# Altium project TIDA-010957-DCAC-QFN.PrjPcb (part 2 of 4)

## Sheet TIDA-010957-DCAC-Switching-Stage-GaN.SchDoc
size 558 x 431 mm; Date: Not shown in title block; ApprovedBy: Not shown in title block; CheckedBy: Not shown in title block; Author: Not shown in title block; CompanyName: Not shown in title block; Engineer: Not shown in title block; Organization: Not shown in title block; Address1: Not shown in title block; Address2: Not shown in title block; Address3: Not shown in title block; Address4: Not shown in title block; DocumentNumber: 1; Revision: Use project parameter SCH_Rev; SheetNumber: 12; SheetTotal: 12; PageSetup: Record=PageOptions¦CenterHorizontal=True¦CenterVertical=True¦PrintScale=1.00¦XCorrection=1.00¦YCorrection=1.00¦PrintKind=0¦BorderSize=5000000¦LeftOffset=0¦BottomOffset=0¦Orientation=2¦PaperLength=1000¦PaperWidth=1000¦Scale=100¦PaperSource=15¦PrintQuality=600¦MediaType=1¦DitherType=10¦PaperKind=Letter¦PrintScaleMode=1
Used 4 times, as channels N, L1, L2, L3. Parts and nets are listed once, with the designators drawn on the sheet.
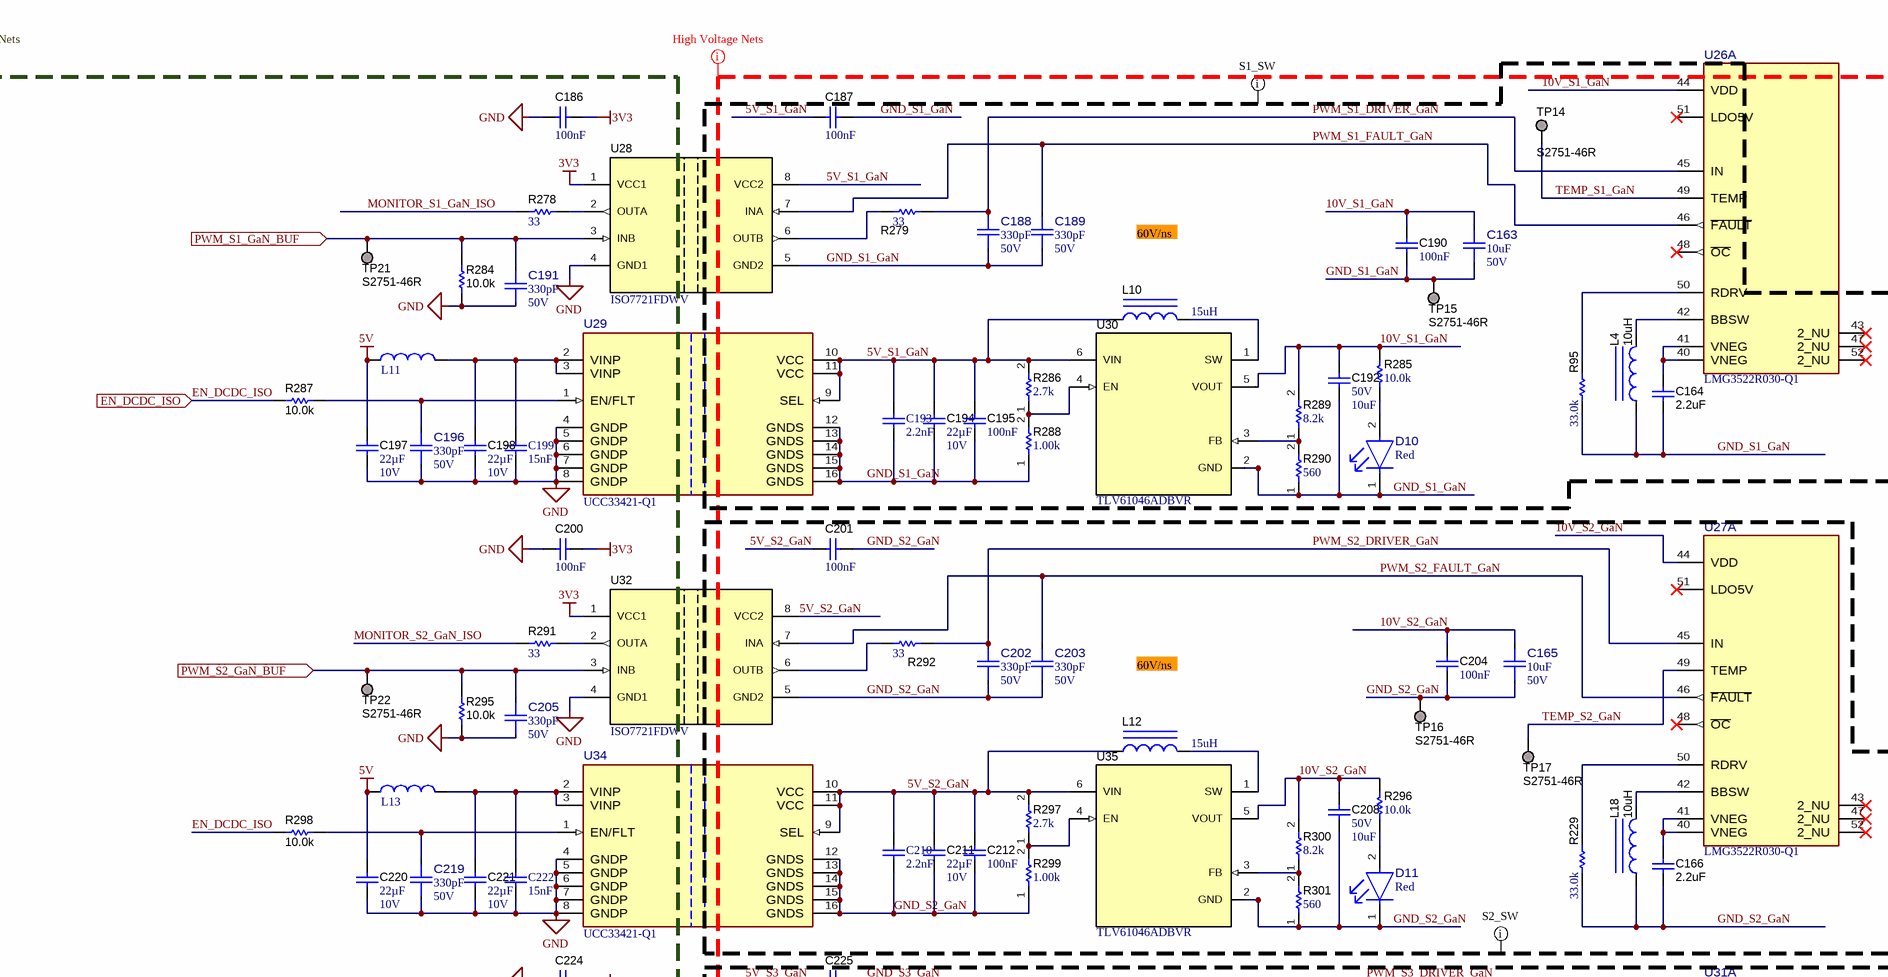
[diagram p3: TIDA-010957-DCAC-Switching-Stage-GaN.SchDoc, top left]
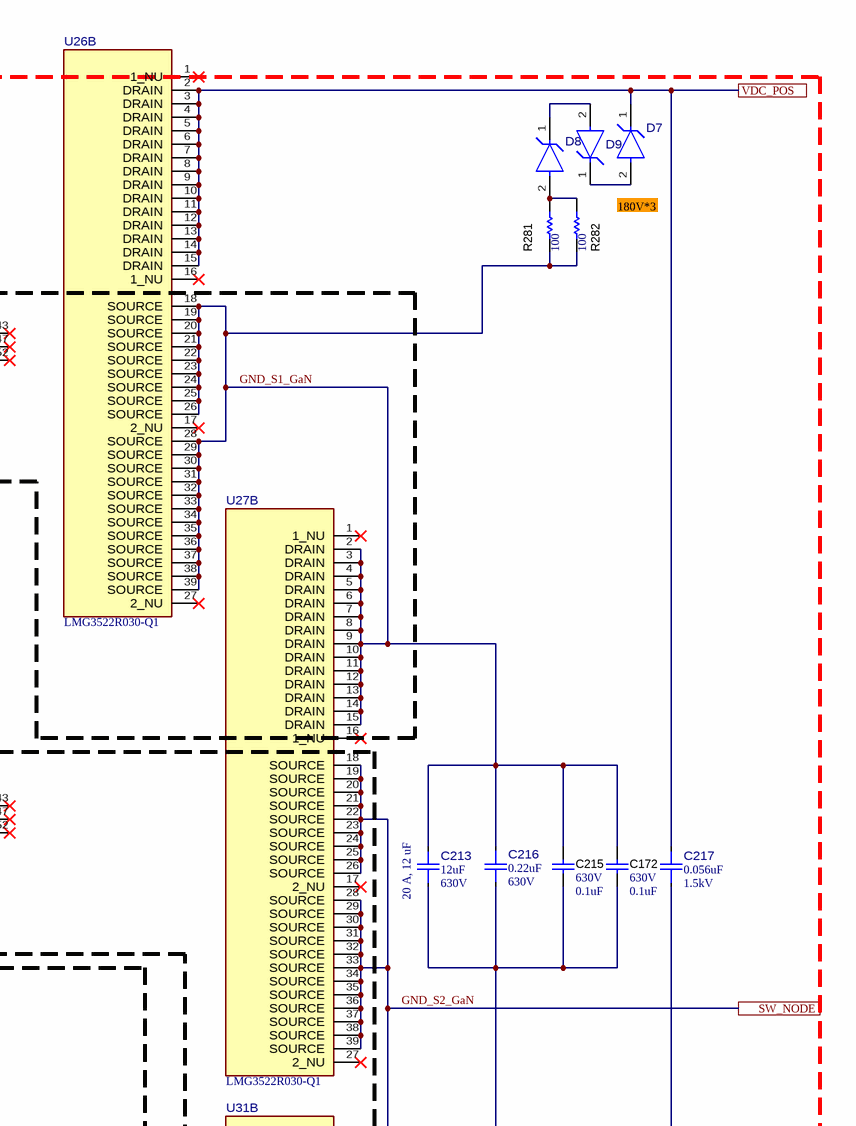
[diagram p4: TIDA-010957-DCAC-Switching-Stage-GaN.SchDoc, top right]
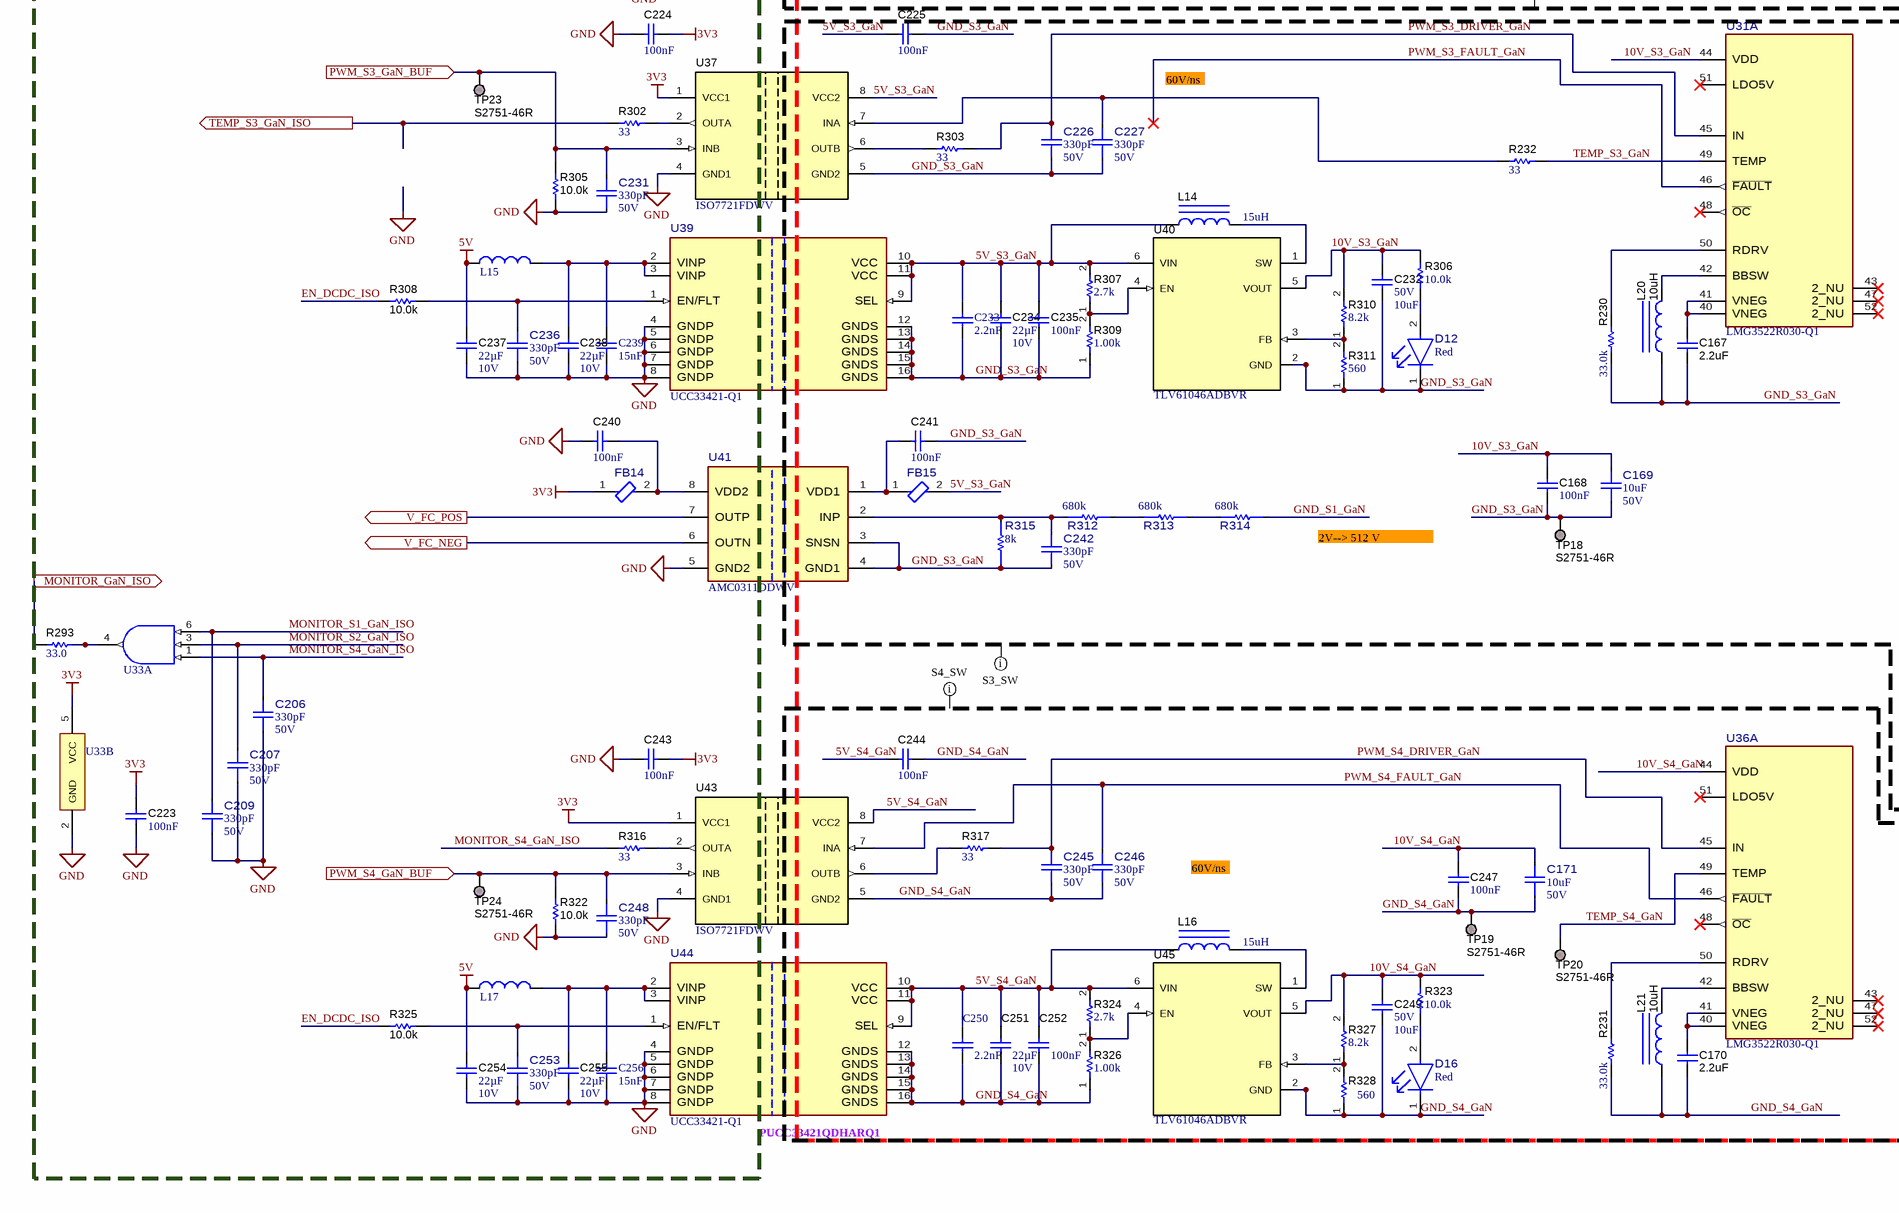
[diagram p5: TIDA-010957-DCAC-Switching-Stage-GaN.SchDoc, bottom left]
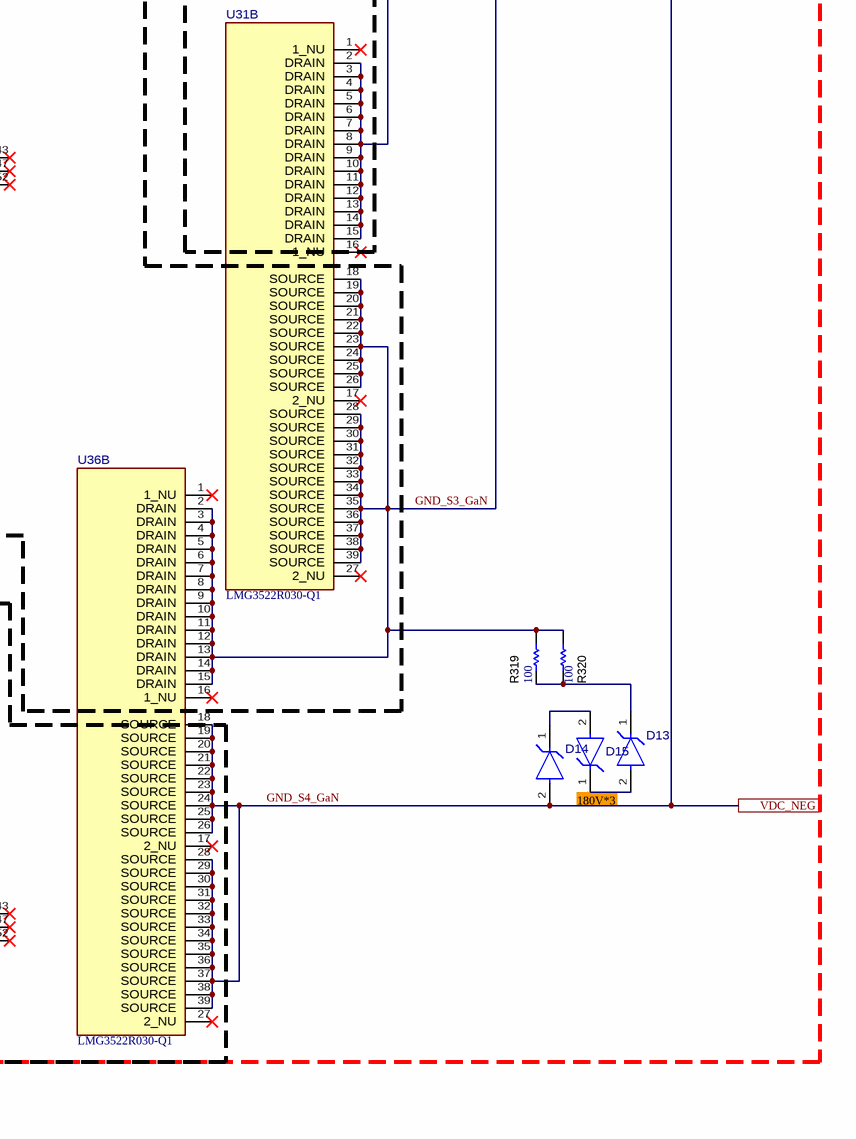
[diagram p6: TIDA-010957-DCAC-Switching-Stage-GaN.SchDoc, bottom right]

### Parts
C163  ValueDisplayed: 10uF  VDC_V: 50V  [FP-GRM21BR61H106ME43L_0805-MFG]  (hidden comment: GRM21BR61H106ME43L)
C164  ValueDisplayed: 2.2uF  [0805_HV]  (hidden comment: GRM21BR71E225KA73L)
C165  ValueDisplayed: 10uF  VDC_V: 50V  [FP-GRM21BR61H106ME43L_0805-MFG]  (hidden comment: GRM21BR61H106ME43L)
C166  ValueDisplayed: 2.2uF  [0805_HV]  (hidden comment: GRM21BR71E225KA73L)
C167  ValueDisplayed: 2.2uF  [0805_HV]  (hidden comment: GRM21BR71E225KA73L)
C168  Cap_F: 100nF  [0603]  (hidden comment: 06033C104JAT2A)
C169  ValueDisplayed: 10uF  VDC_V: 50V  [FP-GRM21BR61H106ME43L_0805-MFG]  (hidden comment: GRM21BR61H106ME43L)
C170  ValueDisplayed: 2.2uF  [0805_HV]  (hidden comment: GRM21BR71E225KA73L)
C171  ValueDisplayed: 10uF  VDC_V: 50V  [FP-GRM21BR61H106ME43L_0805-MFG]  (hidden comment: GRM21BR61H106ME43L)
C172  VDC_V: 630V  ValueDisplayed: 0.1uF  [1812_254]  (hidden comment: C1812X104KBRACTU)
C186  Cap_F: 100nF  [0603]  (hidden comment: 06033C104JAT2A)
C187  Cap_F: 100nF  [0603]  (hidden comment: 06033C104JAT2A)
C188  ValueDisplayed: 330pF  VDC_V: 50V  [FP-CGA3E2C0G1H331J080AA_0603-MFG]  (hidden comment: CGA3E2C0G1H331J080AA)
C189  ValueDisplayed: 330pF  VDC_V: 50V  [FP-CGA3E2C0G1H331J080AA_0603-MFG]  (hidden comment: CGA3E2C0G1H331J080AA)
C190  Cap_F: 100nF  [0603]  (hidden comment: 06033C104JAT2A)
C191  ValueDisplayed: 330pF  VDC_V: 50V  [FP-CGA3E2C0G1H331J080AA_0603-MFG]  (hidden comment: CGA3E2C0G1H331J080AA)
C192  VDC_V: 50V  ValueDisplayed: 10uF  [1206_180]  (hidden comment: GRT31CR61H106KE01L)
C193  Cap_F: 2.2nF  [WCAP-CSGP_0402_L1W0.5H0.5]  (hidden comment: 885012205063)
C194  Cap_F: 22µF  VDC_V: 10V  [0805_HV]  (hidden comment: GRM21BZ71A226ME15L)
C195  Cap_F: 100nF  [0603]  (hidden comment: 06033C104JAT2A)
C196  ValueDisplayed: 330pF  VDC_V: 50V  [FP-CGA3E2C0G1H331J080AA_0603-MFG]  (hidden comment: CGA3E2C0G1H331J080AA)
C197  Cap_F: 22µF  VDC_V: 10V  [0805_HV]  (hidden comment: GRM21BZ71A226ME15L)
C198  Cap_F: 22µF  VDC_V: 10V  [0805_HV]  (hidden comment: GRM21BZ71A226ME15L)
C199  Cap_F: 15nF  [WCAP-CSGP_0402_L1W0.5H0.5]  (hidden comment: 885012205051)
C200  Cap_F: 100nF  [0603]  (hidden comment: 06033C104JAT2A)
C201  Cap_F: 100nF  [0603]  (hidden comment: 06033C104JAT2A)
C202  ValueDisplayed: 330pF  VDC_V: 50V  [FP-CGA3E2C0G1H331J080AA_0603-MFG]  (hidden comment: CGA3E2C0G1H331J080AA)
C203  ValueDisplayed: 330pF  VDC_V: 50V  [FP-CGA3E2C0G1H331J080AA_0603-MFG]  (hidden comment: CGA3E2C0G1H331J080AA)
C204  Cap_F: 100nF  [0603]  (hidden comment: 06033C104JAT2A)
C205  ValueDisplayed: 330pF  VDC_V: 50V  [FP-CGA3E2C0G1H331J080AA_0603-MFG]  (hidden comment: CGA3E2C0G1H331J080AA)
C206  ValueDisplayed: 330pF  VDC_V: 50V  [FP-CGA3E2C0G1H331J080AA_0603-MFG]  (hidden comment: CGA3E2C0G1H331J080AA)
C207  ValueDisplayed: 330pF  VDC_V: 50V  [FP-CGA3E2C0G1H331J080AA_0603-MFG]  (hidden comment: CGA3E2C0G1H331J080AA)
C208  VDC_V: 50V  ValueDisplayed: 10uF  [1206_180]  (hidden comment: GRT31CR61H106KE01L)
C209  ValueDisplayed: 330pF  VDC_V: 50V  [FP-CGA3E2C0G1H331J080AA_0603-MFG]  (hidden comment: CGA3E2C0G1H331J080AA)
C210  Cap_F: 2.2nF  [WCAP-CSGP_0402_L1W0.5H0.5]  (hidden comment: 885012205063)
C211  Cap_F: 22µF  VDC_V: 10V  [0805_HV]  (hidden comment: GRM21BZ71A226ME15L)
C212  Cap_F: 100nF  [0603]  (hidden comment: 06033C104JAT2A)
C213  ValueDisplayed: 12uF  VDC_V: 630V  [FP-B32676G6126K000_RADIAL-MFG]  (hidden comment: B32676G6126K000)
C215  VDC_V: 630V  ValueDisplayed: 0.1uF  [1812_254]  (hidden comment: C1812X104KBRACTU)
C216  ValueDisplayed: 0.22uF  VDC_V: 630V  [FP-C2225C224KBRACTU_2225-MFG]  (hidden comment: C2225C224KBRACTU)
C217  ValueDisplayed: 0.056uF  VDC_V: 1.5kV  [FP-C2225C563KFRACTU_2225-MFG]  (hidden comment: C2225C563KFRACTU)
C219  ValueDisplayed: 330pF  VDC_V: 50V  [FP-CGA3E2C0G1H331J080AA_0603-MFG]  (hidden comment: CGA3E2C0G1H331J080AA)
C220  Cap_F: 22µF  VDC_V: 10V  [0805_HV]  (hidden comment: GRM21BZ71A226ME15L)
C221  Cap_F: 22µF  VDC_V: 10V  [0805_HV]  (hidden comment: GRM21BZ71A226ME15L)
C222  Cap_F: 15nF  [WCAP-CSGP_0402_L1W0.5H0.5]  (hidden comment: 885012205051)
C223  Cap_F: 100nF  [0603]  (hidden comment: 06033C104JAT2A)
C224  Cap_F: 100nF  [0603]  (hidden comment: 06033C104JAT2A)
C225  Cap_F: 100nF  [0603]  (hidden comment: 06033C104JAT2A)
C226  ValueDisplayed: 330pF  VDC_V: 50V  [FP-CGA3E2C0G1H331J080AA_0603-MFG]  (hidden comment: CGA3E2C0G1H331J080AA)
C227  ValueDisplayed: 330pF  VDC_V: 50V  [FP-CGA3E2C0G1H331J080AA_0603-MFG]  (hidden comment: CGA3E2C0G1H331J080AA)
C231  ValueDisplayed: 330pF  VDC_V: 50V  [FP-CGA3E2C0G1H331J080AA_0603-MFG]  (hidden comment: CGA3E2C0G1H331J080AA)
C232  VDC_V: 50V  ValueDisplayed: 10uF  [1206_180]  (hidden comment: GRT31CR61H106KE01L)
C233  Cap_F: 2.2nF  [WCAP-CSGP_0402_L1W0.5H0.5]  (hidden comment: 885012205063)
C234  Cap_F: 22µF  VDC_V: 10V  [0805_HV]  (hidden comment: GRM21BZ71A226ME15L)
C235  Cap_F: 100nF  [0603]  (hidden comment: 06033C104JAT2A)
C236  ValueDisplayed: 330pF  VDC_V: 50V  [FP-CGA3E2C0G1H331J080AA_0603-MFG]  (hidden comment: CGA3E2C0G1H331J080AA)
C237  Cap_F: 22µF  VDC_V: 10V  [0805_HV]  (hidden comment: GRM21BZ71A226ME15L)
C238  Cap_F: 22µF  VDC_V: 10V  [0805_HV]  (hidden comment: GRM21BZ71A226ME15L)
C239  Cap_F: 15nF  [WCAP-CSGP_0402_L1W0.5H0.5]  (hidden comment: 885012205051)
C240  Cap_F: 100nF  [0603]  (hidden comment: 06033C104JAT2A)
C241  Cap_F: 100nF  [0603]  (hidden comment: 06033C104JAT2A)
C242  ValueDisplayed: 330pF  VDC_V: 50V  [FP-CGA3E2C0G1H331J080AA_0603-MFG]  (hidden comment: CGA3E2C0G1H331J080AA)
C243  Cap_F: 100nF  [0603]  (hidden comment: 06033C104JAT2A)
C244  Cap_F: 100nF  [0603]  (hidden comment: 06033C104JAT2A)
C245  ValueDisplayed: 330pF  VDC_V: 50V  [FP-CGA3E2C0G1H331J080AA_0603-MFG]  (hidden comment: CGA3E2C0G1H331J080AA)
C246  ValueDisplayed: 330pF  VDC_V: 50V  [FP-CGA3E2C0G1H331J080AA_0603-MFG]  (hidden comment: CGA3E2C0G1H331J080AA)
C247  Cap_F: 100nF  [0603]  (hidden comment: 06033C104JAT2A)
C248  ValueDisplayed: 330pF  VDC_V: 50V  [FP-CGA3E2C0G1H331J080AA_0603-MFG]  (hidden comment: CGA3E2C0G1H331J080AA)
C249  VDC_V: 50V  ValueDisplayed: 10uF  [1206_180]  (hidden comment: GRT31CR61H106KE01L)
C250  Cap_F: 2.2nF  [WCAP-CSGP_0402_L1W0.5H0.5]  (hidden comment: 885012205063)
C251  Cap_F: 22µF  VDC_V: 10V  [0805_HV]  (hidden comment: GRM21BZ71A226ME15L)
C252  Cap_F: 100nF  [0603]  (hidden comment: 06033C104JAT2A)
C253  ValueDisplayed: 330pF  VDC_V: 50V  [FP-CGA3E2C0G1H331J080AA_0603-MFG]  (hidden comment: CGA3E2C0G1H331J080AA)
C254  Cap_F: 22µF  VDC_V: 10V  [0805_HV]  (hidden comment: GRM21BZ71A226ME15L)
C255  Cap_F: 22µF  VDC_V: 10V  [0805_HV]  (hidden comment: GRM21BZ71A226ME15L)
C256  Cap_F: 15nF  [WCAP-CSGP_0402_L1W0.5H0.5]  (hidden comment: 885012205051)
D7  ZGL41-180A-E3/96  [FP-ZGL41-180A-E3/96_GL41-MFG]  (value not drawn)
D8  ZGL41-180A-E3/96  [FP-ZGL41-180A-E3/96_GL41-MFG]  (value not drawn)
D9  ZGL41-180A-E3/96  [FP-ZGL41-180A-E3/96_GL41-MFG]  (value not drawn)
D10  Color: Red  [FP-APG1608SURKC_T_0603-MFG]  (hidden comment: APG1608SURKC/T)
D11  Color: Red  [FP-APG1608SURKC_T_0603-MFG]  (hidden comment: APG1608SURKC/T)
D12  Color: Red  [FP-APG1608SURKC_T_0603-MFG]  (hidden comment: APG1608SURKC/T)
D13  ZGL41-180A-E3/96  [FP-ZGL41-180A-E3/96_GL41-MFG]  (value not drawn)
D14  ZGL41-180A-E3/96  [FP-ZGL41-180A-E3/96_GL41-MFG]  (value not drawn)
D15  ZGL41-180A-E3/96  [FP-ZGL41-180A-E3/96_GL41-MFG]  (value not drawn)
D16  Color: Red  [FP-APG1608SURKC_T_0603-MFG]  (hidden comment: APG1608SURKC/T)
FB14  MH1608-601Y  [FP-MH1608-601Y_0603-MFG]  (value not drawn)
FB15  MH1608-601Y  [FP-MH1608-601Y_0603-MFG]  (value not drawn)
L4  ValueDisplayed: 10uH  [WE-LQS_2010]  (hidden comment: 74404020100)
L10  ValueDisplayed: 15uH  [SDR0302]  (hidden comment: SDR0302-150ML)
L11  74479763222  [WE-PMI_0603_L1.6W0.8H0.8]  (value not drawn)
L12  ValueDisplayed: 15uH  [SDR0302]  (hidden comment: SDR0302-150ML)
L13  74479763222  [WE-PMI_0603_L1.6W0.8H0.8]  (value not drawn)
L14  ValueDisplayed: 15uH  [SDR0302]  (hidden comment: SDR0302-150ML)
L15  74479763222  [WE-PMI_0603_L1.6W0.8H0.8]  (value not drawn)
L16  ValueDisplayed: 15uH  [SDR0302]  (hidden comment: SDR0302-150ML)
L17  74479763222  [WE-PMI_0603_L1.6W0.8H0.8]  (value not drawn)
L18  ValueDisplayed: 10uH  [WE-LQS_2010]  (hidden comment: 74404020100)
L20  ValueDisplayed: 10uH  [WE-LQS_2010]  (hidden comment: 74404020100)
L21  ValueDisplayed: 10uH  [WE-LQS_2010]  (hidden comment: 74404020100)
R95  ValueDisplayed: 33.0k  [0603]  (hidden comment: RC0603FR-0733KL)
R229  ValueDisplayed: 33.0k  [0603]  (hidden comment: RC0603FR-0733KL)
R230  ValueDisplayed: 33.0k  [0603]  (hidden comment: RC0603FR-0733KL)
R231  ValueDisplayed: 33.0k  [0603]  (hidden comment: RC0603FR-0733KL)
R232  ValueDisplayed: 33  [0603]  (hidden comment: CRCW060333R0JNEA)
R278  ValueDisplayed: 33  [0603]  (hidden comment: CRCW060333R0JNEA)
R279  ValueDisplayed: 33  [0603]  (hidden comment: CRCW060333R0JNEA)
R281  ValueDisplayed: 100  [1206]  (hidden comment: CRCW1206100RFKEAHP)
R282  ValueDisplayed: 100  [1206]  (hidden comment: CRCW1206100RFKEAHP)
R284  ValueDisplayed: 10.0k  [0603]  (hidden comment: CRCW060310K0FKEA)
R285  ValueDisplayed: 10.0k  [0603]  (hidden comment: RC0603FR-0710KL)
R286  ValueDisplayed: 2.7k  [0603]  (hidden comment: CRCW06032K70JNEA)
R287  ValueDisplayed: 10.0k  [0603]  (hidden comment: CRCW060310K0FKEA)
R288  ValueDisplayed: 1.00k  [0603]  (hidden comment: RT0603DRE071KL)
R289  ValueDisplayed: 8.2k  [0603]  (hidden comment: RC0603JR-078K2L)
R290  ValueDisplayed: 560  [0603]  (hidden comment: RC0603JR-07560RL)
R291  ValueDisplayed: 33  [0603]  (hidden comment: CRCW060333R0JNEA)
R292  ValueDisplayed: 33  [0603]  (hidden comment: CRCW060333R0JNEA)
R293  ValueDisplayed: 33.0  [0402L]  (hidden comment: ERJ-2RKF33R0X)
R295  ValueDisplayed: 10.0k  [0603]  (hidden comment: CRCW060310K0FKEA)
R296  ValueDisplayed: 10.0k  [0603]  (hidden comment: RC0603FR-0710KL)
R297  ValueDisplayed: 2.7k  [0603]  (hidden comment: CRCW06032K70JNEA)
R298  ValueDisplayed: 10.0k  [0603]  (hidden comment: CRCW060310K0FKEA)
R299  ValueDisplayed: 1.00k  [0603]  (hidden comment: RT0603DRE071KL)
R300  ValueDisplayed: 8.2k  [0603]  (hidden comment: RC0603JR-078K2L)
R301  ValueDisplayed: 560  [0603]  (hidden comment: RC0603JR-07560RL)
R302  ValueDisplayed: 33  [0603]  (hidden comment: CRCW060333R0JNEA)
R303  ValueDisplayed: 33  [0603]  (hidden comment: CRCW060333R0JNEA)
R305  ValueDisplayed: 10.0k  [0603]  (hidden comment: CRCW060310K0FKEA)
R306  ValueDisplayed: 10.0k  [0603]  (hidden comment: RC0603FR-0710KL)
R307  ValueDisplayed: 2.7k  [0603]  (hidden comment: CRCW06032K70JNEA)
R308  ValueDisplayed: 10.0k  [0603]  (hidden comment: CRCW060310K0FKEA)
R309  ValueDisplayed: 1.00k  [0603]  (hidden comment: RT0603DRE071KL)
R310  ValueDisplayed: 8.2k  [0603]  (hidden comment: RC0603JR-078K2L)
R311  ValueDisplayed: 560  [0603]  (hidden comment: RC0603JR-07560RL)
R312  value 680k  [FP-TNPV0805680KBEEA_0805-MFG]  (hidden comment: TNPV0805680KBEEA)
R313  value 680k  [FP-TNPV0805680KBEEA_0805-MFG]  (hidden comment: TNPV0805680KBEEA)
R314  value 680k  [FP-TNPV0805680KBEEA_0805-MFG]  (hidden comment: TNPV0805680KBEEA)
R315  value 8k  [FP-RT0603BRE078KL_0603-MFG]  (hidden comment: RT0603BRE078KL)
R316  ValueDisplayed: 33  [0603]  (hidden comment: CRCW060333R0JNEA)
R317  ValueDisplayed: 33  [0603]  (hidden comment: CRCW060333R0JNEA)
R319  ValueDisplayed: 100  [1206]  (hidden comment: CRCW1206100RFKEAHP)
R320  ValueDisplayed: 100  [1206]  (hidden comment: CRCW1206100RFKEAHP)
R322  ValueDisplayed: 10.0k  [0603]  (hidden comment: CRCW060310K0FKEA)
R323  ValueDisplayed: 10.0k  [0603]  (hidden comment: RC0603FR-0710KL)
R324  ValueDisplayed: 2.7k  [0603]  (hidden comment: CRCW06032K70JNEA)
R325  ValueDisplayed: 10.0k  [0603]  (hidden comment: CRCW060310K0FKEA)
R326  ValueDisplayed: 1.00k  [0603]  (hidden comment: RT0603DRE071KL)
R327  ValueDisplayed: 8.2k  [0603]  (hidden comment: RC0603JR-078K2L)
R328  ValueDisplayed: 560  [0603]  (hidden comment: RC0603JR-07560RL)
TP14  S2751-46R  [Harwin_S2751-46R]  (no BOM)
TP15  S2751-46R  [Harwin_S2751-46R]  (no BOM)
TP16  S2751-46R  [Harwin_S2751-46R]  (no BOM)
TP17  S2751-46R  [Harwin_S2751-46R]  (no BOM)
TP18  S2751-46R  [Harwin_S2751-46R]  (no BOM)
TP19  S2751-46R  [Harwin_S2751-46R]  (no BOM)
TP20  S2751-46R  [Harwin_S2751-46R]  (no BOM)
TP21  S2751-46R  [Harwin_S2751-46R]  (no BOM)
TP22  S2751-46R  [Harwin_S2751-46R]  (no BOM)
TP23  S2751-46R  [Harwin_S2751-46R]  (no BOM)
TP24  S2751-46R  [Harwin_S2751-46R]  (no BOM)
U26  LMG3522R030-Q1  [RQS0052C-C01-MFG]  (parts A,B of 2)
U27  LMG3522R030-Q1  [RQS0052C-C01-MFG]  (parts A,B of 2)
U28  ISO7721FDWV  [DWV0008A]
U29  UCC33421-Q1  [DWX0016A-MFG]
U30  TLV61046ADBVR  [DBV0006A_N]
U31  LMG3522R030-Q1  [RQS0052C-C01-MFG]  (parts A,B of 2)
U32  ISO7721FDWV  [DWV0008A]
U33  SN74LVC1G11DBVR  [DBV0006A_N]  (value not drawn)  (parts A,B of 2)
U34  UCC33421-Q1  [DWX0016A-MFG]
U35  TLV61046ADBVR  [DBV0006A_N]
U36  LMG3522R030-Q1  [RQS0052C-C01-MFG]  (parts A,B of 2)
U37  ISO7721FDWV  [DWV0008A]
U39  UCC33421-Q1  [DWX0016A-MFG]
U40  TLV61046ADBVR  [DBV0006A_N]
U41  AMC0311DDWV  [DWV0008A-MFG]
U43  ISO7721FDWV  [DWV0008A]
U44  UCC33421-Q1  [DWX0016A-MFG]
U45  TLV61046ADBVR  [DBV0006A_N]

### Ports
EN_DCDC_ISO (in), MONITOR_GaN_ISO (out), PWM_S1_GaN_BUF (in), PWM_S2_GaN_BUF (in), PWM_S3_GaN_BUF (in), PWM_S4_GaN_BUF (in), SW_NODE, TEMP_S3_GaN_ISO (out), V_FC_NEG (out), V_FC_POS (out), VDC_NEG, VDC_POS

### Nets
3V3: C186.1 C200.1 C223.1 C224.1 C243.1 FB14.1 U28.1(VCC1) U32.1(VCC1) U33.5(VCC) U37.1(VCC1) U43.1(VCC1)
5V: C197.1 C220.1 C237.1 C254.1 L11.2 L13.2 L15.2 L17.2
GND: C186.2 C191.1 C196.1 C197.2 C198.2 C199.1 C200.2 C205.1 C206.1 C207.1 C209.1 C219.1 C220.2 C221.2 C222.1 C223.2 C224.2 C231.1 C236.1 C237.2 C238.2 C239.1 C240.2 C243.2 C248.1 C253.1 C254.2 C255.2 C256.1 R284.1 R295.1 R305.1 R322.1 U28.4(GND1) U29.4(GNDP) U29.5(GNDP) U29.6(GNDP) U29.7(GNDP) U29.8(GNDP) U32.4(GND1) U33.2(GND) U34.4(GNDP) U34.5(GNDP) U34.6(GNDP) U34.7(GNDP) U34.8(GNDP) U37.4(GND1) U39.4(GNDP) U39.5(GNDP) U39.6(GNDP) U39.7(GNDP) U39.8(GNDP) U41.5(GND2) U43.4(GND1) U44.4(GNDP) U44.5(GNDP) U44.6(GNDP) U44.7(GNDP) U44.8(GNDP)
5V_S1_GaN: C187.1 C193.2 C194.1 C195.1 L10.2 R286.2 U28.8(VCC2) U29.9(SEL) U29.10(VCC) U29.11(VCC) U30.6(VIN)
5V_S2_GaN: C201.1 C210.2 C211.1 C212.1 L12.2 R297.2 U32.8(VCC2) U34.9(SEL) U34.10(VCC) U34.11(VCC) U35.6(VIN)
5V_S3_GaN: C225.1 C233.2 C234.1 C235.1 FB15.2 L14.2 R307.2 U37.8(VCC2) U39.9(SEL) U39.10(VCC) U39.11(VCC) U40.6(VIN)
5V_S4_GaN: C244.1 C250.2 C251.1 C252.1 L16.2 R324.2 U43.8(VCC2) U44.9(SEL) U44.10(VCC) U44.11(VCC) U45.6(VIN)
10V_S1_GaN: C163.2 C190.1 C192.1 R285.2 R289.2 U26.44(VDD) U30.5(VOUT)
10V_S2_GaN: C165.2 C204.1 C208.1 R296.2 R300.2 U27.44(VDD) U35.5(VOUT)
10V_S3_GaN: C168.1 C169.2 C232.1 R306.2 R310.2 U31.44(VDD) U40.5(VOUT)
10V_S4_GaN: C171.2 C247.1 C249.1 R323.2 R327.2 U36.44(VDD) U45.5(VOUT)
EN_DCDC_ISO: R287.2 R298.2 R308.2 R325.2 ; port EN_DCDC_ISO
GND_S1_GaN: C163.1 C164.2 C172.1 C187.2 C188.1 C189.1 C190.2 C192.2 C193.1 C194.2 C195.2 C213.2 C215.1 C216.1 D10.1(CATHODE) L4.1 R95.2 R281.1 R282.1 R288.1 R290.1 R314.2 TP15.1 U26.18(SOURCE) U26.19(SOURCE) U26.20(SOURCE) U26.21(SOURCE) U26.22(SOURCE) U26.23(SOURCE) U26.24(SOURCE) U26.25(SOURCE) U26.26(SOURCE) U26.28(SOURCE) U26.29(SOURCE) U26.30(SOURCE) U26.31(SOURCE) U26.32(SOURCE) U26.33(SOURCE) U26.34(SOURCE) U26.35(SOURCE) U26.36(SOURCE) U26.37(SOURCE) U26.38(SOURCE) U26.39(SOURCE) U27.2(DRAIN) U27.3(DRAIN) U27.4(DRAIN) U27.5(DRAIN) U27.6(DRAIN) U27.7(DRAIN) U27.8(DRAIN) U27.9(DRAIN) U27.10(DRAIN) U27.11(DRAIN) U27.12(DRAIN) U27.13(DRAIN) U27.14(DRAIN) U27.15(DRAIN) U28.5(GND2) U29.12(GNDS) U29.13(GNDS) U29.14(GNDS) U29.15(GNDS) U29.16(GNDS) U30.2(GND)
GND_S2_GaN: C165.1 C166.2 C201.2 C202.1 C203.1 C204.2 C208.2 C210.1 C211.2 C212.2 D11.1(CATHODE) L18.1 R229.2 R299.1 R301.1 TP16.1 U27.18(SOURCE) U27.19(SOURCE) U27.20(SOURCE) U27.21(SOURCE) U27.22(SOURCE) U27.23(SOURCE) U27.24(SOURCE) U27.25(SOURCE) U27.26(SOURCE) U27.28(SOURCE) U27.29(SOURCE) U27.30(SOURCE) U27.31(SOURCE) U27.32(SOURCE) U27.33(SOURCE) U27.34(SOURCE) U27.35(SOURCE) U27.36(SOURCE) U27.37(SOURCE) U27.38(SOURCE) U27.39(SOURCE) U31.2(DRAIN) U31.3(DRAIN) U31.4(DRAIN) U31.5(DRAIN) U31.6(DRAIN) U31.7(DRAIN) U31.8(DRAIN) U31.9(DRAIN) U31.10(DRAIN) U31.11(DRAIN) U31.12(DRAIN) U31.13(DRAIN) U31.14(DRAIN) U31.15(DRAIN) U32.5(GND2) U34.12(GNDS) U34.13(GNDS) U34.14(GNDS) U34.15(GNDS) U34.16(GNDS) U35.2(GND) ; port SW_NODE
GND_S3_GaN: C167.2 C168.2 C169.1 C172.2 C213.1 C215.2 C216.2 C225.2 C226.1 C227.1 C232.2 C233.1 C234.2 C235.2 C241.2 C242.1 D12.1(CATHODE) L20.1 R230.2 R309.1 R311.1 R315.1 R319.2 R320.2 TP18.1 U31.18(SOURCE) U31.19(SOURCE) U31.20(SOURCE) U31.21(SOURCE) U31.22(SOURCE) U31.23(SOURCE) U31.24(SOURCE) U31.25(SOURCE) U31.26(SOURCE) U31.28(SOURCE) U31.29(SOURCE) U31.30(SOURCE) U31.31(SOURCE) U31.32(SOURCE) U31.33(SOURCE) U31.34(SOURCE) U31.35(SOURCE) U31.36(SOURCE) U31.37(SOURCE) U31.38(SOURCE) U31.39(SOURCE) U36.2(DRAIN) U36.3(DRAIN) U36.4(DRAIN) U36.5(DRAIN) U36.6(DRAIN) U36.7(DRAIN) U36.8(DRAIN) U36.9(DRAIN) U36.10(DRAIN) U36.11(DRAIN) U36.12(DRAIN) U36.13(DRAIN) U36.14(DRAIN) U36.15(DRAIN) U37.5(GND2) U39.12(GNDS) U39.13(GNDS) U39.14(GNDS) U39.15(GNDS) U39.16(GNDS) U40.2(GND) U41.3(SNSN) U41.4(GND1)
GND_S4_GaN: C170.2 C171.1 C217.1 C244.2 C245.1 C246.1 C247.2 C249.2 C250.1 C251.2 C252.2 D14.2(ANODE) D16.1(CATHODE) L21.1 R231.2 R326.1 R328.1 TP19.1 U36.18(SOURCE) U36.19(SOURCE) U36.20(SOURCE) U36.21(SOURCE) U36.22(SOURCE) U36.23(SOURCE) U36.24(SOURCE) U36.25(SOURCE) U36.26(SOURCE) U36.28(SOURCE) U36.29(SOURCE) U36.30(SOURCE) U36.31(SOURCE) U36.32(SOURCE) U36.33(SOURCE) U36.34(SOURCE) U36.35(SOURCE) U36.36(SOURCE) U36.37(SOURCE) U36.38(SOURCE) U36.39(SOURCE) U43.5(GND2) U44.12(GNDS) U44.13(GNDS) U44.14(GNDS) U44.15(GNDS) U44.16(GNDS) U45.2(GND) ; port VDC_NEG
MONITOR_GaN_ISO: R293.1 ; port MONITOR_GaN_ISO
MONITOR_S1_GaN_ISO: C209.2 R278.1 U33.6(C)
MONITOR_S2_GaN_ISO: C207.2 R291.1 U33.3(B)
MONITOR_S4_GaN_ISO: C206.2 R316.1 U33.1(A)
PWM_S1_DRIVER_GaN: C188.2 R279.2 U26.45(IN)
PWM_S1_FAULT_GaN: C189.2 U26.46(~{FAULT}) U28.7(INA)
PWM_S1_GaN_BUF: C191.2 R284.2 TP21.1 U28.3(INB) ; port PWM_S1_GaN_BUF
PWM_S2_DRIVER_GaN: C202.2 R292.2 U27.45(IN)
PWM_S2_FAULT_GaN: C203.2 U27.46(~{FAULT}) U32.7(INA)
PWM_S2_GaN_BUF: C205.2 R295.2 TP22.1 U32.3(INB) ; port PWM_S2_GaN_BUF
PWM_S3_DRIVER_GaN: C226.2 R303.2 U31.45(IN)
PWM_S3_FAULT_GaN: U31.46(~{FAULT})
PWM_S3_GaN_BUF: C231.2 R305.2 TP23.1 U37.3(INB) ; port PWM_S3_GaN_BUF
PWM_S4_DRIVER_GaN: C245.2 R317.2 U36.45(IN)
PWM_S4_FAULT_GaN: C246.2 U36.46(~{FAULT}) U43.7(INA)
PWM_S4_GaN_BUF: C248.2 R322.2 TP24.1 U43.3(INB) ; port PWM_S4_GaN_BUF
TEMP_S1_GaN: TP14.1 U26.49(TEMP)
TEMP_S2_GaN: TP17.1 U27.49(TEMP)
TEMP_S3_GaN: R232.2 U31.49(TEMP)
TEMP_S3_GaN_ISO: R302.1 ; port TEMP_S3_GaN_ISO
TEMP_S4_GaN: TP20.1 U36.49(TEMP)
V_FC_NEG: U41.6(OUTN) ; port V_FC_NEG
V_FC_POS: U41.7(OUTP) ; port V_FC_POS
VDC_POS: C217.2 D7.1(CATHODE) U26.2(DRAIN) U26.3(DRAIN) U26.4(DRAIN) U26.5(DRAIN) U26.6(DRAIN) U26.7(DRAIN) U26.8(DRAIN) U26.9(DRAIN) U26.10(DRAIN) U26.11(DRAIN) U26.12(DRAIN) U26.13(DRAIN) U26.14(DRAIN) U26.15(DRAIN) ; port VDC_POS
NetC164_1: C164.1 U26.40(VNEG) U26.41(VNEG)
NetC166_1: C166.1 U27.40(VNEG) U27.41(VNEG)
NetC167_1: C167.1 U31.40(VNEG) U31.41(VNEG)
NetC170_1: C170.1 U36.40(VNEG) U36.41(VNEG)
NetC196_2: C196.2 R287.1 U29.1(EN/FLT)
NetC198_1: C198.1 C199.2 L11.1 U29.2(VINP) U29.3(VINP)
NetC219_2: C219.2 R298.1 U34.1(EN/FLT)
NetC221_1: C221.1 C222.2 L13.1 U34.2(VINP) U34.3(VINP)
NetC227_2: C227.2 R232.1 U37.7(INA)
NetC236_2: C236.2 R308.1 U39.1(EN/FLT)
NetC238_1: C238.1 C239.2 L15.1 U39.2(VINP) U39.3(VINP)
NetC240_1: C240.1 FB14.2 U41.8(VDD2)
NetC241_1: C241.1 FB15.1 U41.1(VDD1)
NetC242_2: C242.2 R312.1 R315.2 U41.2(INP)
NetC253_2: C253.2 R325.1 U44.1(EN/FLT)
NetC255_1: C255.1 C256.2 L17.1 U44.2(VINP) U44.3(VINP)
NetD7_2: D7.2(ANODE) D9.1(CATHODE)
NetD8_1: D8.1(CATHODE) D9.2(ANODE)
NetD8_2: D8.2(ANODE) R281.2 R282.2
NetD10_2: D10.2(ANODE) R285.1
NetD11_2: D11.2(ANODE) R296.1
NetD12_2: D12.2(ANODE) R306.1
NetD13_1: D13.1(CATHODE) R319.1 R320.1
NetD13_2: D13.2(ANODE) D15.1(CATHODE)
NetD14_1: D14.1(CATHODE) D15.2(ANODE)
NetD16_2: D16.2(ANODE) R323.1
NetL4_2: L4.2 U26.42(BBSW)
NetL10_1: L10.1 U30.1(SW)
NetL12_1: L12.1 U35.1(SW)
NetL14_1: L14.1 U40.1(SW)
NetL16_1: L16.1 U45.1(SW)
NetL18_2: L18.2 U27.42(BBSW)
NetL20_2: L20.2 U31.42(BBSW)
NetL21_2: L21.2 U36.42(BBSW)
NetR95_1: R95.1 U26.50(RDRV)
NetR229_1: R229.1 U27.50(RDRV)
NetR230_1: R230.1 U31.50(RDRV)
NetR231_1: R231.1 U36.50(RDRV)
NetR278_2: R278.2 U28.2(OUTA)
NetR279_1: R279.1 U28.6(OUTB)
NetR286_1: R286.1 R288.2 U30.4(EN)
NetR289_1: R289.1 R290.2 U30.3(FB)
NetR291_2: R291.2 U32.2(OUTA)
NetR292_1: R292.1 U32.6(OUTB)
NetR293_2: R293.2 U33.4(Y)
NetR297_1: R297.1 R299.2 U35.4(EN)
NetR300_1: R300.1 R301.2 U35.3(FB)
NetR302_2: R302.2 U37.2(OUTA)
NetR303_1: R303.1 U37.6(OUTB)
NetR307_1: R307.1 R309.2 U40.4(EN)
NetR310_1: R310.1 R311.2 U40.3(FB)
NetR312_2: R312.2 R313.1
NetR313_2: R313.2 R314.1
NetR316_2: R316.2 U43.2(OUTA)
NetR317_1: R317.1 U43.6(OUTB)
NetR324_1: R324.1 R326.2 U45.4(EN)
NetR327_1: R327.1 R328.2 U45.3(FB)

Not connected (* = marked no-connect by the designer): U26 1(1_NU)* 16(1_NU)* 17(2_NU)* 27(2_NU)* 43(2_NU)* 47(2_NU)* 48(~{OC})* 51(LDO5V)* 52(2_NU)*; U27 1(1_NU)* 16(1_NU)* 17(2_NU)* 27(2_NU)* 43(2_NU)* 47(2_NU)* 48(~{OC})* 51(LDO5V)* 52(2_NU)*; U31 1(1_NU)* 16(1_NU)* 17(2_NU)* 27(2_NU)* 43(2_NU)* 47(2_NU)* 48(~{OC})* 51(LDO5V)* 52(2_NU)*; U36 1(1_NU)* 16(1_NU)* 17(2_NU)* 27(2_NU)* 43(2_NU)* 47(2_NU)* 48(~{OC})* 51(LDO5V)* 52(2_NU)*

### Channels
N: designators end in _N; ports EN_DCDC_ISO=EN_AUX_ISO_DCAC MONITOR_GaN_ISO=MONITOR_GaN_ISO_N PWM_S1_GaN_BUF=PWM_S1_GaN_BUF_N PWM_S2_GaN_BUF=PWM_S2_GaN_BUF_N PWM_S3_GaN_BUF=PWM_S3_GaN_BUF_N PWM_S4_GaN_BUF=PWM_S4_GaN_BUF_N SW_NODE=GND_S2_GaN TEMP_S3_GaN_ISO=TEMP_S3_GaN_ISO_N V_FC_NEG=V_FC_NEG_N V_FC_POS=V_FC_POS_N VDC_NEG=GND_S4_GaN VDC_POS=VDC+
L1: designators end in _L1; ports EN_DCDC_ISO=EN_AUX_ISO_DCAC MONITOR_GaN_ISO=MONITOR_GaN_ISO_L1 PWM_S1_GaN_BUF=PWM_S1_GaN_BUF_L1 PWM_S2_GaN_BUF=PWM_S2_GaN_BUF_L1 PWM_S3_GaN_BUF=PWM_S3_GaN_BUF_L1 PWM_S4_GaN_BUF=PWM_S4_GaN_BUF_L1 SW_NODE=GND_S2_GaN TEMP_S3_GaN_ISO=TEMP_S3_GaN_ISO_L1 V_FC_NEG=V_FC_NEG_L1 V_FC_POS=V_FC_POS_L1 VDC_NEG=GND_S4_GaN VDC_POS=VDC+
L2: designators end in _L2; ports EN_DCDC_ISO=EN_AUX_ISO_DCAC MONITOR_GaN_ISO=MONITOR_GaN_ISO_L2 PWM_S1_GaN_BUF=PWM_S1_GaN_BUF_L2 PWM_S2_GaN_BUF=PWM_S2_GaN_BUF_L2 PWM_S3_GaN_BUF=PWM_S3_GaN_BUF_L2 PWM_S4_GaN_BUF=PWM_S4_GaN_BUF_L2 SW_NODE=GND_S2_GaN TEMP_S3_GaN_ISO=TEMP_S3_GaN_ISO_L2 V_FC_NEG=V_FC_NEG_L2 V_FC_POS=V_FC_POS_L2 VDC_NEG=GND_S4_GaN VDC_POS=VDC+
L3: designators end in _L3; ports EN_DCDC_ISO=EN_AUX_ISO_DCAC MONITOR_GaN_ISO=MONITOR_GaN_ISO_L3 PWM_S1_GaN_BUF=PWM_S1_GaN_BUF_L3 PWM_S2_GaN_BUF=PWM_S2_GaN_BUF_L3 PWM_S3_GaN_BUF=PWM_S3_GaN_BUF_L3 PWM_S4_GaN_BUF=PWM_S4_GaN_BUF_L3 SW_NODE=GND_S2_GaN TEMP_S3_GaN_ISO=TEMP_S3_GaN_ISO_L3 V_FC_NEG=V_FC_NEG_L3 V_FC_POS=V_FC_POS_L3 VDC_NEG=GND_S4_GaN VDC_POS=VDC+

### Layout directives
net class LV_NET: 3V3, 5V, EN_DCDC_ISO, GND, MONITOR_S1_GaN_ISO, MONITOR_S2_GaN_ISO, MONITOR_S4_GaN_ISO
net class HV_NET: 5V_S1_GaN, 5V_S2_GaN, 5V_S3_GaN, 5V_S4_GaN, 10V_S1_GaN, 10V_S2_GaN, 10V_S3_GaN, 10V_S4_GaN, GND_S1_GaN, GND_S2_GaN, GND_S3_GaN, GND_S4_GaN, PWM_S1_DRIVER_GaN, PWM_S1_FAULT_GaN, PWM_S2_DRIVER_GaN, PWM_S2_FAULT_GaN, PWM_S3_DRIVER_GaN, PWM_S3_FAULT_GaN, PWM_S4_DRIVER_GaN, PWM_S4_FAULT_GaN, TEMP_S1_GaN, TEMP_S2_GaN, TEMP_S3_GaN, TEMP_S4_GaN
net class S4_SW: 5V_S1_GaN, 5V_S2_GaN, 5V_S3_GaN, 5V_S4_GaN, 10V_S1_GaN, 10V_S2_GaN, 10V_S3_GaN, 10V_S4_GaN, GND_S1_GaN, GND_S2_GaN, GND_S3_GaN, GND_S4_GaN, PWM_S1_DRIVER_GaN, PWM_S1_FAULT_GaN, PWM_S2_DRIVER_GaN, PWM_S2_FAULT_GaN, PWM_S3_DRIVER_GaN, PWM_S3_FAULT_GaN, PWM_S4_DRIVER_GaN, PWM_S4_FAULT_GaN, TEMP_S1_GaN, TEMP_S2_GaN, TEMP_S3_GaN, TEMP_S4_GaN
net class S3_SW: 5V_S1_GaN, 5V_S2_GaN, 5V_S3_GaN, 5V_S4_GaN, 10V_S1_GaN, 10V_S2_GaN, 10V_S3_GaN, 10V_S4_GaN, GND_S1_GaN, GND_S2_GaN, GND_S3_GaN, GND_S4_GaN, PWM_S1_DRIVER_GaN, PWM_S1_FAULT_GaN, PWM_S2_DRIVER_GaN, PWM_S2_FAULT_GaN, PWM_S3_DRIVER_GaN, PWM_S3_FAULT_GaN, PWM_S4_DRIVER_GaN, PWM_S4_FAULT_GaN, TEMP_S1_GaN, TEMP_S2_GaN, TEMP_S3_GaN, TEMP_S4_GaN
net class S2_SW: 5V_S1_GaN, 5V_S2_GaN, 5V_S3_GaN, 5V_S4_GaN, 10V_S1_GaN, 10V_S2_GaN, 10V_S3_GaN, 10V_S4_GaN, GND_S1_GaN, GND_S2_GaN, GND_S3_GaN, GND_S4_GaN, PWM_S1_DRIVER_GaN, PWM_S1_FAULT_GaN, PWM_S2_DRIVER_GaN, PWM_S2_FAULT_GaN, PWM_S3_DRIVER_GaN, PWM_S3_FAULT_GaN, PWM_S4_DRIVER_GaN, PWM_S4_FAULT_GaN, TEMP_S1_GaN, TEMP_S2_GaN, TEMP_S3_GaN, TEMP_S4_GaN
net class S1_SW: 5V_S1_GaN, 5V_S2_GaN, 5V_S3_GaN, 5V_S4_GaN, 10V_S1_GaN, 10V_S2_GaN, 10V_S3_GaN, 10V_S4_GaN, GND_S1_GaN, GND_S2_GaN, GND_S3_GaN, GND_S4_GaN, PWM_S1_DRIVER_GaN, PWM_S1_FAULT_GaN, PWM_S2_DRIVER_GaN, PWM_S2_FAULT_GaN, PWM_S3_DRIVER_GaN, PWM_S3_FAULT_GaN, PWM_S4_DRIVER_GaN, PWM_S4_FAULT_GaN, TEMP_S1_GaN, TEMP_S2_GaN, TEMP_S3_GaN, TEMP_S4_GaN

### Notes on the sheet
- 180V*3
- 60V/ns
- (near C213) 20 A, 12 uF
- 2V--> 512 V
- (near U44) PUCC33421QDHARQ1

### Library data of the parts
C163 C165 C169 C171 = CMP-0095280-1: Chip Multilayer Ceramic Capacitors for General Purpose, 0805, 10uF, X5R, 15%, 20%, 50V; Manufacturer: Murata; Cap_F: 10µF; AEC Qualified: No; SizeZ_mm: 1.45mm; Value: 10µF
C164 C166 C167 C170 = CMP-0008342-2: CAP, CERM, 2.2 uF, 25 V, +/- 10%, X7R, 0805; Manufacturer: MuRata; Alternate PartNumber: GRM219R61E225KA12D; Polarized: N; Value: 2.2uF; U/M: EA; Cap_F: 2.2µF; ESR_ohm: 5m; Value1: 0.005 ohm; VDC_V: 25V; TaMin_C: -55°C; TaMax_C: 125°C; Cap_Case: 0805; SizeArea_mm2: 2.5; SizeAreaWB_mm2: 6.75; SizeX_mm: 2; SizeY_mm: 1.25; SizeZ_mm: 1.45; AEC Category: Q200
C168 C186 C187 C190 C195 C200 C201 C204 C212 C223-C225 C235 C240 C241 C243 C244 C247 C252 = CMP-0006752-5: CAP, CERM, 0.1 uF, 25 V, +/- 5%, X7R, 0603; Manufacturer: AVX; TaMin_C: -55°C; ESR_ohm: 0.05; Polarized: N; SizeAreaWB_mm2: 4.68; Value1: 0.05 ohm; U/M: EA; Value: 0.1uF; TaMax_C: 125°C; SizeZ_mm: 1; SizeX_mm: 1.6; SizeY_mm: 0.8; Value2: 25V; SizeArea_mm2: 1.28; AEC Category: Q200
C172 C215 = CMP-0009327-2: CAP, CERM, 0.1 uF, 630 V, +/- 10%, X7R, 1812; Manufacturer: Kemet; TaMin_C: -55°C; Polarized: N; SizeAreaWB_mm2: 23.1; Value1: Unknown; U/M: EA; Value: 0.1uF; TaMax_C: 125°C; SizeZ_mm: 2.54; SizeX_mm: 4.5; SizeY_mm: 3.2; Cap_Case: 1812; SizeArea_mm2: 14.4; Cap_F: 100nF; AEC Category: Q200
C188 C189 C191 C196 C202 C203 C205-C207 C209 C219 C226 C227 C231 C236 C242 C245 C246 C248 C253 = CMP-0095085-1: Cap Ceramic 330pF 50V C0G 5% Pad SMD 0603 +125°C Automotive T/R; Manufacturer: TDK; AEC Qualified: Yes; TempCo: 30ppm/°C; Tolerance_%: 0.05%; AEC Grade: Grade 1; SizeZ_mm: 1.1mm
C192 C208 C232 C249 = CMP-0009015-2: CAP, CERM, 10 uF, 50 V, +/- 10%, X5R, AEC-Q200 Grade 1, 1206; Manufacturer: MuRata; TaMin_C: -55°C; Polarized: N; SizeAreaWB_mm2: 10.92; Value1: Unknown; U/M: EA; Value: 10uF; TaMax_C: 85°C; SizeZ_mm: 1.8; SizeX_mm: 3.2; SizeY_mm: 1.6; Cap_Case: 1206; SizeArea_mm2: 5.12; AEC Qualified: Y; Cap_F: 10µF; AEC Grade: 1; AEC Category: Q200
C193 C210 C233 C250 = CMP-0119293-1: WCAP-CSGP Multilayer Ceramic Chip Capacitor, General Purpose, size 0402, X7R, 2.2nF, 50VDC; Manufacturer: Wurth Elektronik; Capacitance Tolerance: +/-10%; Case/Size Code: 0402; Dissipation Factor: 2.5%; Insulation Resistance: 10GOhm; Rated Voltage (DC): 50V; Technical Reference: X7R0402222K050DFCT10000
C194 C197 C198 C211 C220 C221 C234 C237 C238 C251 C254 C255 = CMP-0008377-2: CAP, CERM, 22 uF, 10 V, +/- 20%, X7R, 0805; Manufacturer: MuRata; SizeY_mm: 1.25; Cap_Case: 0805; SizeArea_mm2: 2.5; AEC Qualified: N; AEC Category: Q200; ValueDisplayed: 22uF; TaMin_C: -55°C; SizeAreaWB_mm2: 6.75; Value1: Unknown; U/M: EA; Value: 22uF; TaMax_C: 125°C; SizeZ_mm: 1.45; SizeX_mm: 2
C199 C222 C239 C256 = CMP-0115362-1: WCAP-CSGP Multilayer Ceramic Chip Capacitor, General Purpose, size 0402, X7R, 15nF, 25VDC; Manufacturer: Wurth Elektronik; Capacitance Tolerance: +/-10%; Case/Size Code: 0402; Dissipation Factor: 3.5%; Insulation Resistance: 10GOhm; Rated Voltage (DC): 25V; Technical Reference: X7R0402153K025DFCT10000
C213 = CMP-0124359-1: Cap Film 12uF 630V PP 10% (42 X 28 X 42.5mm) Radial 0.0055 Ohm 100°C Bulk; Manufacturer: TDK; AEC Grade: Grade 2; AEC Qualified: Yes; Cap_F: 12µF; Value: 12µF
C216 = CMP-0126491-1: Ceramic Capacitor, Multilayer, Ceramic, 630V, 10% +Tol, 10% -Tol, X7R, 15% TC, 0.22uF, Surface Mount, 2225; Manufacturer: KEMET; AEC Qualified: No; Cap_F: 220nF; SizeZ_mm: 1.8mm; Value: 220nF
C217 = CMP-0126492-1: 0.056 µF ±10% 1500V (1.5kV) Ceramic Capacitor X7R 2225 (5763 Metric); Manufacturer: KEMET; AEC Qualified: No; Cap_F: 56nF; SizeZ_mm: 1.8mm; TempCo: 15%; Value: 56nF
D7-D9 D13-D15 = CMP-0122312-1: Zener Diode 180 V 1 W ±5% Surface Mount DO-213AB (GL41); Manufacturer: Vishay; AEC Qualified: No; SizeZ_mm: 2.67mm; TJmax_C: 150°C; Vf_V: 189V; Vr_V: 136.9V; Max Reverse Leakage Current: 1uA; Power_W: 1000mW; Vz_V: 180V; Zener Impedance: 900Ω
D10-D12 D16 = CMP-0091305-2: Red 630nm LED Indication - Discrete 2V 0603 (1608 Metric); Manufacturer: Kingbright; AEC Qualified: No; Import Ts: 1521847491; Forward Current: 20mA; Vr_V: 5V; Ciiva Ids: 1546259; Luminous Intensity: 110mcd; Power_TotalModule: 75mW; Tjmax_C: 115°C; Led Orientation: Top View; SizeZ_mm: 0.28mm; LambdaP: 645nm; Angle: 120°
FB14 FB15 = CMP-0037505-1: 600 Ohms @ 100 MHz 1 Power, Signal Line Ferrite Bead 0603 (1608 Metric) 1A 200mOhm; Manufacturer: Bourns; DCR_ohm: 0.2; SizeZ_mm: 1mm; AEC Qualified: No; Impedance At Frequency: 600Ω @ 100MHz; Test Frequency: 100MHz; Tolerance_%: 25%
L4 L18 L20 L21 = CMP-0063789-1: Inductor, 10 uH, 0.5 A, 0.85 ohm, SMD; Manufacturer: Wurth Elektronik; Value: 10uH; Ind_H: 10µH; Imax_A: 5dA; Irms: 0.5A @ 40C rise; Isat: 0.6A @ 30% inductance drop; DCR_ohm: 8.5d; Value2: 0.5A; SizeAreaWB_mm2: 7.8; SizeArea_mm2: 3.2; SizeX_mm: 2; SizeY_mm: 1.6; SizeZ_mm: 1; AEC Category: Q200; AEC Qualified: N
L10 L12 L14 L16 = CMP-0057419-2: Inductor, Drum Core, Ferrite, 15 uH, 0.65 A, 0.4 ohm, SMD; Manufacturer: Bourns; Isat: 0.86A @ 10% inductance drop; Irms: 0.65A @ 40C rise; Green_Lifecycle: Active; SizeAreaWB_mm2: 15.2; DCR_ohm: 4d; Green_REACh: Passed; Value1: 0.4 ohm; Value: 15uH; Imax_A: 6.5dA; SizeZ_mm: 2.5; SizeX_mm: 3; SizeY_mm: 2.8; Value2: 0.65A; SizeArea_mm2: 8.4; Ind_H: 15µH; AEC Category: Q200
L11 L13 L15 L17 = CMP-0100992-1: WE-PMI SMT Power Multilayer Inductor, size 0603, 2.2uH, 0.8A, 375mOhm; Manufacturer: Wurth Elektronik; Case/Size Code: 0603; Inductance Tolerance: 20%; Q Factor: 15; Saturation Current: 0.28A; Self Resonant Frequency: 80MHz; Type: Low RDC
R95 R229-R231 = CMP-0023037-5: RES, 33.0 k, 1%, 0.1 W, 0603; Manufacturer: Yageo; Power_W: 100mW; TempCo: 100 ppm/C; Value_Code: 33k0; Value: 33.0k; Res_ohm: 33k; SizeX_mm: 1.6; SizeY_mm: 0.8; SizeZ_mm: 1; Value2: 0.1W; SizeArea_mm2: 1.28; AEC Qualified: N; VDC_V: 75V; AEC Category: Q200; SizeAreaWB_mm2: 4.68
R232 R278 R279 R291 R292 R302 R303 R316 R317 = CMP-0025787-4: RES, 33, 5%, 0.1 W, AEC-Q200 Grade 0, 0603; Manufacturer: Vishay-Dale; Power_W: 100mW; TempCo: 200 ppm/C; Value_Code: 33R0; Value: 33; EIA_Code: E24; SizeX_mm: 1.6; SizeY_mm: 0.8; SizeZ_mm: 1; Value2: 0.1W; SizeArea_mm2: 1.28; AEC Qualified: Y; VDC_V: 75V; AEC Category: Q200; AEC Grade: 0
R281 R282 R319 R320 = CMP-0016570-3: RES, 100, 1%, 0.5 W, AEC-Q200 Grade 0, 1206; Manufacturer: Vishay-Dale; Power_W: 500mW; TempCo: 100 ppm/C; Value_Code: 100R; Value: 100; EIA_Code: E96; SizeX_mm: 3.2; SizeY_mm: 1.6; SizeZ_mm: 1.35; Value2: 0.5W; SizeArea_mm2: 5.12; AEC Qualified: Y; AEC Grade: 0; AEC Category: Q200
R284 R287 R295 R298 R305 R308 R322 R325 = CMP-0021998-4: RES, 10.0 k, 1%, 0.1 W, AEC-Q200 Grade 0, 0603; Manufacturer: Vishay-Dale; Power_W: 100mW; TempCo: 100 ppm/C; Value_Code: 10k0; Value: 10.0k; EIA_Code: E96; Res_ohm: 10k; SizeX_mm: 1.6; SizeY_mm: 0.8; SizeZ_mm: 1; Value2: 0.1W; SizeArea_mm2: 1.28; AEC Qualified: Y; VDC_V: 75V; AEC Category: Q200; AEC Grade: 0
R285 R296 R306 R323 = CMP-0022746-5: RES, 10.0 k, 1%, 0.1 W, 0603; Manufacturer: Yageo; Power_W: 100mW; TempCo: 100 ppm/C; Value_Code: 10k0; Value: 10.0k; EIA_Code: E96; Res_ohm: 10k; SizeX_mm: 1.6; SizeY_mm: 0.8; SizeZ_mm: 1; Value2: 0.1W; SizeArea_mm2: 1.28; AEC Qualified: N; VDC_V: 75V; AEC Category: Q200; SizeAreaWB_mm2: 4.68
R286 R297 R307 R324 = CMP-0025771-4: RES, 2.7 k, 5%, 0.1 W, AEC-Q200 Grade 0, 0603; Manufacturer: Vishay-Dale; Power_W: 100mW; TempCo: 200 ppm/C; Value_Code: 2k70; Value: 2.7k; EIA_Code: E24; SizeX_mm: 1.6; SizeY_mm: 0.8; SizeZ_mm: 1; Value2: 0.1W; SizeArea_mm2: 1.28; AEC Qualified: Y; VDC_V: 75V; AEC Category: Q200; AEC Grade: 0
R288 R299 R309 R326 = CMP-0024852-2: RES, 1.00 k, 0.5%, 0.1 W, 0603; Manufacturer: Yageo America; Power_W: 100mW; TempCo: 50 ppm/C; Value_Code: 1k00; U/M: EA; Value: 1.00k; EIA_Code: E192; Res_ohm: 1k; SizeX_mm: 1.6; SizeY_mm: 0.8; SizeZ_mm: 1; Value2: 0.1W; SizeArea_mm2: 1.28; VDC_V: 75V; AEC Category: Q200
R289 R300 R310 R327 = CMP-0025942-5: RES, 8.2 k, 5%, 0.1 W, 0603; Manufacturer: Yageo; Power_W: 100mW; TempCo: 100 ppm/C; Value_Code: 8k20; Value: 8.2k; EIA_Code: E24; SizeX_mm: 1.6; SizeY_mm: 0.8; SizeZ_mm: 1; Value2: 0.1W; SizeArea_mm2: 1.28; AEC Qualified: N; VDC_V: 75V; AEC Category: Q200; SizeAreaWB_mm2: 4.68
R290 R301 R311 R328 = CMP-0025930-5: RES, 560, 5%, 0.1 W, 0603; Manufacturer: Yageo; Power_W: 100mW; TempCo: 100 ppm/C; Value_Code: 560R; Value: 560; EIA_Code: E24; SizeX_mm: 1.6; SizeY_mm: 0.8; SizeZ_mm: 1; Value2: 0.1W; SizeArea_mm2: 1.28; AEC Qualified: N; VDC_V: 75V; AEC Category: Q200; SizeAreaWB_mm2: 4.68
R293 = CMP-0026696-1: RES, 33.0, 1%, 0.1 W, 0402; Manufacturer: Panasonic; Power_W: 100mW; TempCo: 100 ppm/C; Value_Code: 33R0; U/M: EA; Value: 33.0; Res_ohm: 33; SizeX_mm: 1; SizeY_mm: 0.5; SizeZ_mm: 0.6; Value2: 0.1W; VDC_V: 50V; AEC Category: Q200
R312-R314 = CMP-0124370-1: 680 kOhms ±0.1% 0.2W, 1/5W Chip Resistor 0805 (2012 Metric) Anti-Sulfur, Automotive AEC-Q200, High Voltage, Moisture Resistant Thin Film; Manufacturer: Vishay; AEC Grade: Grade 1; AEC Qualified: Yes; Power_W: 200mW; SizeZ_mm: 0.55mm; TempCo: 25ppm/°C; VDC_V: 450V
R315 = CMP-0122747-1: 8 kOhms ±0.1% 0.1W, 1/10W Chip Resistor 0603 (1608 Metric) Thin Film; Manufacturer: Yageo; AEC Qualified: No; Power_W: 100mW; SizeZ_mm: 0.55mm; TempCo: 50ppm/°C; VDC_V: 75V
TP14-TP24 = CMP-0003968-1: Test Point, SMT; Manufacturer: Harwin
U26 U27 U31 U36 = CMP-0094891-2: 650-V 30-mΩ GaN FET with Integrated Driver, Protection, and Temperature Reporting; Manufacturer: Texas Instruments; Max Supply Voltage: 18V; TaMax_C: +125°C; TaMin_C: -40°C; Nominal Supply Current: 16mA; Number Of Outputs: 1; Standoff Height: 0mm; Min Supply Voltage: 7.5V; TJmax_C: +150°C; AEC Grade: Grade 1; SizeZ_mm: 1mm; Output Voltage: 520V; AEC Qualified: Yes; AEC Category: Q200; CompType: IC
U28 U32 U37 U43 = CMP-0085676-1: High Speed, Robust EMC Reinforced Dual-Channel Digital Isolator, DWV0008A (SOIC-8); Alternate Manufacturer: Texas Instruments; Alternate PartNumber: ISO7721FDWVR; Rating: Catalog; SizeX_mm: 11.5; SizeArea_mm2: 67.275; CompType: IC; AEC Qualified: N; SizeY_mm: 5.85; SizeAreaWB_mm2: 105.975; SizeZ_mm: 2.8; AEC Category: Q200
U29 U34 U39 U44 = CMP-0120108-2: 1.5W, High-Density, >5 kVRMS Isolated DC-DC Converter; Manufacturer: Texas Instruments; SizeZ_mm: 2.6mm; AEC Qualified: No; Max Supply Voltage: 5.5V; Min Supply Voltage: 4.5V; Number Of Outputs: 1; Output Type: AdjustableProgrammable; Output Voltage: 5/5.5V; Standoff Height: 0.14mm; AEC Category: Q200; CompType: IC
U30 U35 U40 U45 = CMP-0013231-2: 28-V Output Voltage Boost Converter with Power Diode and Isolation Switch, DBV0006A (SOT-6); Manufacturer: Texas Instruments; Alternate PartNumber: TLV61046ADBVT; SizeX_mm: 2.8; SizeY_mm: 2.9; CompType: IC; SizeZ_mm: 1.45; SizeArea_mm2: 8.12; SizeAreaWB_mm2: 14.82; U/M: EA
U33 = CMP-0051219-1: Single 3-Input Positive-AND Gate, DBV0006A, LARGE T&R; Manufacturer: Texas Instruments; Output Type: CMOS; Voltage(Nom)(V): 1.8,2.5,3.3,5; ICC @ Nom Voltage(Max)(mA): 0.01; VCC(Min)(V): 1.65; Output Drive (IOL/IOH)(Max)(mA): 32/-32; Schmitt Trigger: No; Input Type: CMOS/TTL; VCC(Max)(V): 5.5; Gate Type: AND; Rating: Catalog; tpd @ Nom Voltage(Max)(ns): 20,7.8,6.2,4.6; Bits(#): 1; F @ Nom Voltage(Max)(Mhz): 150; Logic: True; Technology Family: LVC
U41 = CMP-0124047-1: Precision, 2V Input, Basic and Reinforced Isolated Amplifiers With Fixed-Gain Differential Output; Manufacturer: Texas Instruments; SizeZ_mm: 2.8mm; AEC Qualified: No; Bandwidth: 110kHz; Input Bias Current: 3.5nA; Input Offset Voltage: 0.2mV; Max Supply Voltage: 5.5V; Min Supply Voltage: 3V; Number Of Channels: 1; Output Current Per Channel: 11mA; Response Time: 50us; Standoff Height: 0.36mm; TaMax_C: +125°C; TaMin_C: -40°C; TJmax_C: +150°C; Voltage Gain: 1V/V

## Sheet TIDA-010957-DCAC-EMI-Filter.SchDoc
size 431 x 279 mm; Date: Not shown in title block; ApprovedBy: Not shown in title block; CheckedBy: Not shown in title block; Author: Not shown in title block; CompanyName: Not shown in title block; Engineer: Not shown in title block; Organization: Not shown in title block; Address1: Not shown in title block; Address2: Not shown in title block; Address3: Not shown in title block; Address4: Not shown in title block; DocumentNumber: 2; Revision: Use project parameter SCH_Rev; SheetNumber: 5; SheetTotal: 12; PageSetup: Record=PageOptions¦CenterHorizontal=True¦CenterVertical=True¦PrintScale=1.00¦XCorrection=1.00¦YCorrection=1.00¦PrintKind=0¦BorderSize=5000000¦LeftOffset=0¦BottomOffset=0¦Orientation=2¦PaperLength=1000¦PaperWidth=1000¦Scale=100¦PaperSource=15¦PrintQuality=600¦MediaType=1¦DitherType=10¦PaperKind=Letter¦PrintScaleMode=1
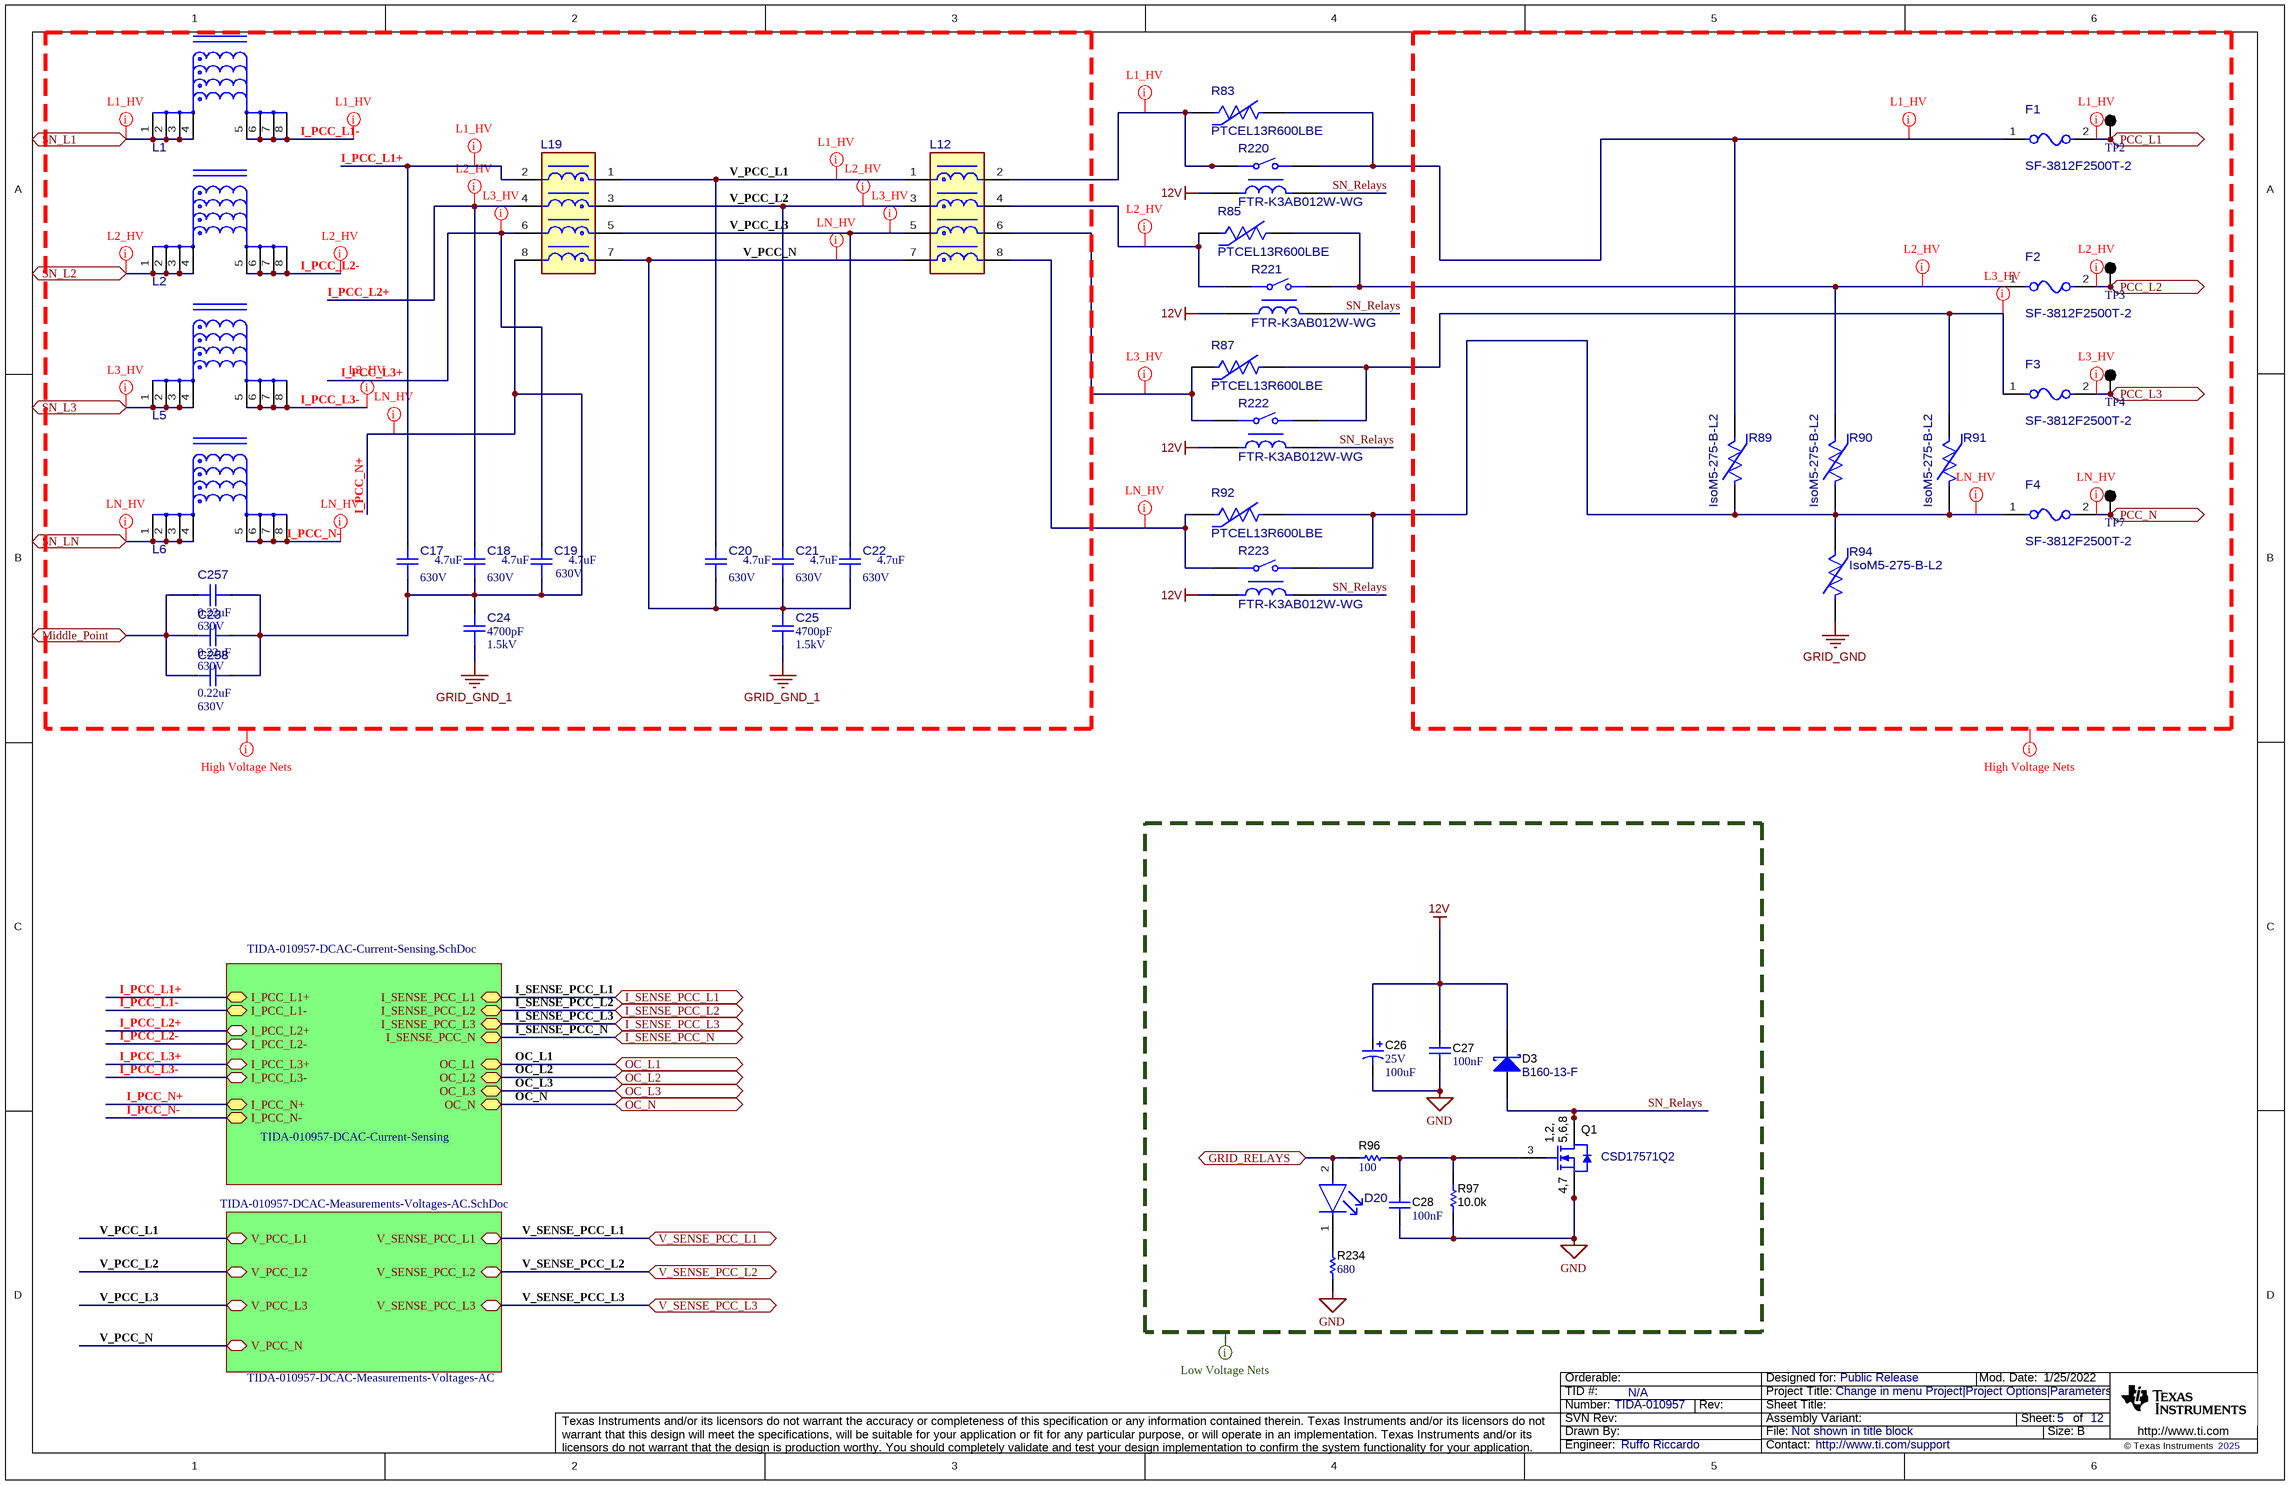
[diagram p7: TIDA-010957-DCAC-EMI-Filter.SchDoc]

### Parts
C17  ValueDisplayed: 4.7uF  VDC_V: 630V  [FP-R523R447050P1M_RADIAL-MFG]  (hidden comment: R523R447050P1M)
C18  ValueDisplayed: 4.7uF  VDC_V: 630V  [FP-R523R447050P1M_RADIAL-MFG]  (hidden comment: R523R447050P1M)
C19  ValueDisplayed: 4.7uF  VDC_V: 630V  [FP-R523R447050P1M_RADIAL-MFG]  (hidden comment: R523R447050P1M)
C20  ValueDisplayed: 4.7uF  VDC_V: 630V  [FP-R523R447050P1M_RADIAL-MFG]  (hidden comment: R523R447050P1M)
C21  ValueDisplayed: 4.7uF  VDC_V: 630V  [FP-R523R447050P1M_RADIAL-MFG]  (hidden comment: R523R447050P1M)
C22  ValueDisplayed: 4.7uF  VDC_V: 630V  [FP-R523R447050P1M_RADIAL-MFG]  (hidden comment: R523R447050P1M)
C23  ValueDisplayed: 0.22uF  VDC_V: 630V  [FP-C2225C224KBRACTU_2225-MFG]  (hidden comment: C2225C224KBRACTU)
C24  ValueDisplayed: 4700pF  VDC_V: 1.5kV  [FP-R413F147050T1K_RADIAL-MFG]  (hidden comment: R413F147050T1K)
C25  ValueDisplayed: 4700pF  VDC_V: 1.5kV  [FP-R413F147050T1K_RADIAL-MFG]  (hidden comment: R413F147050T1K)
C26  VDC_V: 25V  ValueDisplayed: 100uF  [FM_630x1120]  (hidden comment: EEU-FM1E101)
C27  Cap_F: 100nF  [0603]  (hidden comment: 06033C104JAT2A)
C28  Cap_F: 100nF  [0603]  (hidden comment: 06033C104JAT2A)
C257  ValueDisplayed: 0.22uF  VDC_V: 630V  [FP-C2225C224KBRACTU_2225-MFG]  (hidden comment: C2225C224KBRACTU)
C258  ValueDisplayed: 0.22uF  VDC_V: 630V  [FP-C2225C224KBRACTU_2225-MFG]  (hidden comment: C2225C224KBRACTU)
D3  B160-13-F  [SMA]
D20  KG DELLS1.22-JGKH-24  [FP-KG DELLS1.22-JGKH-24_0603-MFG]  (value not drawn)
F1  SF-3812F2500T-2  [FP-SF-3812F2500T-2_SMD2-MFG]
F2  SF-3812F2500T-2  [FP-SF-3812F2500T-2_SMD2-MFG]
F3  SF-3812F2500T-2  [FP-SF-3812F2500T-2_SMD2-MFG]
F4  SF-3812F2500T-2  [FP-SF-3812F2500T-2_SMD2-MFG]
L1  MAG-3002584  [FP-MAG-3002584_PTH8-MFG]  (value not drawn)
L2  MAG-3002584  [FP-MAG-3002584_PTH8-MFG]  (value not drawn)
L5  MAG-3002584  [FP-MAG-3002584_PTH8-MFG]  (value not drawn)
L6  MAG-3002584  [FP-MAG-3002584_PTH8-MFG]  (value not drawn)
L12  MAG-3002585  [FP-MAG-3002585_PTH8-MFG]  (value not drawn)
L19  MAG-3002585  [FP-MAG-3002585_PTH8-MFG]  (value not drawn)
Q1  CSD17571Q2  [DQK0006C]
R83  PTCEL13R600LBE  [FP-PTCEL13R600LBE_RADIAL-MFG]
R85  PTCEL13R600LBE  [FP-PTCEL13R600LBE_RADIAL-MFG]
R87  PTCEL13R600LBE  [FP-PTCEL13R600LBE_RADIAL-MFG]
R89  IsoM5-275-B-L2  [FP-IsoM5-275-B-L2_RADIAL-MFG]
R90  IsoM5-275-B-L2  [FP-IsoM5-275-B-L2_RADIAL-MFG]
R91  IsoM5-275-B-L2  [FP-IsoM5-275-B-L2_RADIAL-MFG]
R92  PTCEL13R600LBE  [FP-PTCEL13R600LBE_RADIAL-MFG]
R94  IsoM5-275-B-L2  [FP-IsoM5-275-B-L2_RADIAL-MFG]
R96  ValueDisplayed: 100  [0402L]  (hidden comment: ERJ-2RKF1000X)
R97  ValueDisplayed: 10.0k  [0603]  (hidden comment: CRCW060310K0FKEA)
R220  FTR-K3AB012W-WG  [FP-FTR-K3AB012W-WG_PTH_RELAY_30MM1_15MM7-MFG]
R221  FTR-K3AB012W-WG  [FP-FTR-K3AB012W-WG_PTH_RELAY_30MM1_15MM7-MFG]
R222  FTR-K3AB012W-WG  [FP-FTR-K3AB012W-WG_PTH_RELAY_30MM1_15MM7-MFG]
R223  FTR-K3AB012W-WG  [FP-FTR-K3AB012W-WG_PTH_RELAY_30MM1_15MM7-MFG]
R234  ValueDisplayed: 680  [0603]  (hidden comment: RC0603JR-07680RL)
TP2  5011  [Keystone5011]  (value not drawn)
TP3  5011  [Keystone5011]  (value not drawn)
TP4  5011  [Keystone5011]  (value not drawn)
TP7  5011  [Keystone5011]  (value not drawn)

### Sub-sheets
TIDA-010957-DCAC-Current-Sensing = TIDA-010957-DCAC-Current-Sensing.SchDoc: I_SENSE_PCC_L1 (bidir), I_SENSE_PCC_L2 (bidir), I_SENSE_PCC_L3 (bidir), I_PCC_L1+ (bidir), I_PCC_L1- (bidir), I_PCC_L2+ (bidir), I_PCC_L2- (bidir), I_PCC_L3+ (bidir), I_PCC_L3- (bidir), OC_L1 (bidir), OC_L2 (bidir), OC_L3 (bidir), I_PCC_N+ (bidir), I_PCC_N- (bidir), OC_N (bidir), I_SENSE_PCC_N (bidir)
TIDA-010957-DCAC-Measurements-Voltages-AC = TIDA-010957-DCAC-Measurements-Voltages-AC.SchDoc: V_PCC_L1 (bidir), V_PCC_N (bidir), V_PCC_L2 (bidir), V_PCC_L3 (bidir), V_SENSE_PCC_L1 (bidir), V_SENSE_PCC_L2 (bidir), V_SENSE_PCC_L3 (bidir)

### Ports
GRID_RELAYS (bidir), I_SENSE_PCC_L1 (bidir), I_SENSE_PCC_L2 (bidir), I_SENSE_PCC_L3 (bidir), I_SENSE_PCC_N (bidir), Middle_Point (bidir), OC_L1 (bidir), OC_L2 (bidir), OC_L3 (bidir), OC_N (bidir), PCC_L1 (bidir), PCC_L2 (bidir), PCC_L3 (bidir), PCC_N (bidir), SN_L1 (bidir), SN_L2 (bidir), SN_L3 (bidir), SN_LN (bidir), V_SENSE_PCC_L1 (bidir), V_SENSE_PCC_L2 (bidir), V_SENSE_PCC_L3 (bidir)

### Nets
12V: C26.1(+) C27.1 D3.1(K) R220.1 R221.1 R222.1 R223.1
GND: C26.2(-) C27.2 C28.2 Q1.4(S) Q1.7(S) R97.1 R234.1
GRID_GND: R94.1
GRID_GND_1: C24.1 C25.1
GND_S2_GaN: L6.1 L6.2 L6.3 L6.4 ; port SN_LN
GND_S2_GaN: L1.1 L1.2 L1.3 L1.4 ; port SN_L1  [a separate net that carries the same name]
GND_S2_GaN: L2.1 L2.2 L2.3 L2.4 ; port SN_L2  [a separate net that carries the same name]
GND_S2_GaN: L5.1 L5.2 L5.3 L5.4 ; port SN_L3  [a separate net that carries the same name]
GRID_RELAYS: D20.2(ANODE) R96.1 ; port GRID_RELAYS
I_PCC_L1+: C17.2 L19.2 ; sheet TIDA-010957-DCAC-Current-Sensing/I_PCC_L1+
I_PCC_L1-: L1.5 L1.6 L1.7 L1.8 ; sheet TIDA-010957-DCAC-Current-Sensing/I_PCC_L1-
I_PCC_L2+: C18.2 L19.4 ; sheet TIDA-010957-DCAC-Current-Sensing/I_PCC_L2+
I_PCC_L2-: L2.5 L2.6 L2.7 L2.8 ; sheet TIDA-010957-DCAC-Current-Sensing/I_PCC_L2-
I_PCC_L3+: C19.2 L19.6 ; sheet TIDA-010957-DCAC-Current-Sensing/I_PCC_L3+
I_PCC_L3-: L5.5 L5.6 L5.7 L5.8 ; sheet TIDA-010957-DCAC-Current-Sensing/I_PCC_L3-
I_PCC_N+: C17.1 C18.1 C19.1 C23.1 C24.2 C257.1 C258.1 L19.8 ; sheet TIDA-010957-DCAC-Current-Sensing/I_PCC_N+
I_PCC_N-: L6.5 L6.6 L6.7 L6.8 ; sheet TIDA-010957-DCAC-Current-Sensing/I_PCC_N-
I_SENSE_PCC_L1: port I_SENSE_PCC_L1, sheet TIDA-010957-DCAC-Current-Sensing/I_SENSE_PCC_L1
I_SENSE_PCC_L2: port I_SENSE_PCC_L2, sheet TIDA-010957-DCAC-Current-Sensing/I_SENSE_PCC_L2
I_SENSE_PCC_L3: port I_SENSE_PCC_L3, sheet TIDA-010957-DCAC-Current-Sensing/I_SENSE_PCC_L3
I_SENSE_PCC_N: port I_SENSE_PCC_N, sheet TIDA-010957-DCAC-Current-Sensing/I_SENSE_PCC_N
Middle_Point: C23.2 C257.2 C258.2 ; port Middle_Point
OC_L1: port OC_L1, sheet TIDA-010957-DCAC-Current-Sensing/OC_L1
OC_L2: port OC_L2, sheet TIDA-010957-DCAC-Current-Sensing/OC_L2
OC_L3: port OC_L3, sheet TIDA-010957-DCAC-Current-Sensing/OC_L3
OC_N: port OC_N, sheet TIDA-010957-DCAC-Current-Sensing/OC_N
PCC_L1: F1.2 TP2.1 ; port PCC_L1
PCC_L2: F2.2 TP3.1 ; port PCC_L2
PCC_L3: F3.2 TP4.1 ; port PCC_L3
PCC_N: F4.2 TP7.1 ; port PCC_N
SN_Relays: D3.2(A) Q1.1(D) Q1.2(D) Q1.5(D) Q1.6(D) Q1.8(D) R220.2 R221.2 R222.2 R223.2
V_PCC_L1: C20.2 L12.1 L19.1 ; sheet TIDA-010957-DCAC-Measurements-Voltages-AC/V_PCC_L1
V_PCC_L2: C21.2 L12.3 L19.3 ; sheet TIDA-010957-DCAC-Measurements-Voltages-AC/V_PCC_L2
V_PCC_L3: C22.2 L12.5 L19.5 ; sheet TIDA-010957-DCAC-Measurements-Voltages-AC/V_PCC_L3
V_PCC_N: C20.1 C21.1 C22.1 C25.2 L12.7 L19.7 ; sheet TIDA-010957-DCAC-Measurements-Voltages-AC/V_PCC_N
V_SENSE_PCC_L1: port V_SENSE_PCC_L1, sheet TIDA-010957-DCAC-Measurements-Voltages-AC/V_SENSE_PCC_L1
V_SENSE_PCC_L2: port V_SENSE_PCC_L2, sheet TIDA-010957-DCAC-Measurements-Voltages-AC/V_SENSE_PCC_L2
V_SENSE_PCC_L3: port V_SENSE_PCC_L3, sheet TIDA-010957-DCAC-Measurements-Voltages-AC/V_SENSE_PCC_L3
NetC28_1: C28.1 Q1.3(G) R96.2 R97.2
NetD20_1: D20.1(CATHODE) R234.2
NetF1_1: F1.1 R83.2 R89.2 R220.4
NetF2_1: F2.1 R85.2 R90.2 R221.4
NetF3_1: F3.1 R87.2 R91.2 R222.4
NetF4_1: F4.1 R89.1 R90.1 R91.1 R92.2 R94.2 R223.4
NetL12_2: L12.2 R83.1 R220.3
NetL12_4: L12.4 R85.1 R221.3
NetL12_6: L12.6 R87.1 R222.3
NetL12_8: L12.8 R92.1 R223.3

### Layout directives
net class LV_NET: 12V, GND, SN_Relays
net class HV_NET: GRID_GND, GRID_GND_1, I_PCC_L1+, I_PCC_L1-, I_PCC_L2+, I_PCC_L2-, I_PCC_L3+, I_PCC_L3-, I_PCC_N+, I_PCC_N-, V_PCC_L1, V_PCC_L2, V_PCC_L3, V_PCC_N
net class L2_HV: GND_S2_GaN, I_PCC_L2+, I_PCC_L2-, NetF2_1, NetL12_4, PCC_L2, V_PCC_L2
net class L1_HV: GND_S2_GaN, I_PCC_L1+, I_PCC_L1-, NetF1_1, NetL12_2, PCC_L1, V_PCC_L1
net class L3_HV: GND_S2_GaN, I_PCC_L3+, I_PCC_L3-, NetF3_1, NetL12_6, PCC_L3, V_PCC_L3
net class LN_HV: GND_S2_GaN, I_PCC_N+, I_PCC_N-, NetF4_1, NetL12_8, PCC_N, V_PCC_N

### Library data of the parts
C17-C22 = CMP-0098409-1: 4.7 µF Film Capacitor 310V 630V Polypropylene (PP), Metallized Radial; Manufacturer: KEMET; AEC Grade: Grade 2; AEC Qualified: Yes; Cap_F: 4.7µF; SizeZ_mm: 28.1mm; Tolerance_%: 20%; VAC_X: X2; Value: 4.7µF
C23 C257 C258 = CMP-0126491-1: as C216 on sheet TIDA-010957-DCAC-Switching-Stage-GaN
C24 C25 = CMP-0098408-1: Cap Film 0.0047uF 1500V PP 10% Dipped 10mm 125°C Bulk; Manufacturer: KEMET; AEC Grade: Grade 1; AEC Qualified: Yes; Cap_F: 4.7nF; SizeZ_mm: 11.1mm; VAC: 300V; VAC_Y: Y2; Value: 4.7nF
C26 = CMP-0010339-1: CAP, AL, 100 uF, 25 V, +/- 20%, 0.13 ohm, TH; Manufacturer: Panasonic; TaMin_C: -40°C; ESR_ohm: 0.13; Polarized: Y; SizeAreaWB_mm2: 68.89; U/M: EA; Value: 100uF; TaMax_C: 105°C; SizeZ_mm: 12.7; SizeX_mm: 6.3; Cap_Case: 6.3x11.2; SizeArea_mm2: 39.69; CompType: Capacitor; AEC Qualified: N; Cap_F: 100µF; IRMS_A: 455mA; AEC Category: Q200
C27 C28 = CMP-0006752-5: as C168 on sheet TIDA-010957-DCAC-Switching-Stage-GaN
D3 = CMP-0028389-2: Diode, Schottky, 60 V, 1 A, SMA; Manufacturer: Diodes Inc.; Green_Lifecycle: Not Set; SizeAreaWB_mm2: 37.3428; Green_REACh: Incomplete; TJmax_C: 150°C; AEC Category: Q101; SizeZ_mm: 2.87; RJC_CperW: 20; Io_A: 1A; SizeArea_mm2: 16.3228; Vf_V: 700mV; Value2: 0.7V; SizeY_mm: 2.92; Vr_V: 60V; SizeX_mm: 5.59; Value: 60V
D20 = CMP-0093310-1: Standard LEDs - SMD Green TOPLED E 1608; Manufacturer: Osram Opto; AEC Grade: Grade 2; LambdaP: 572nm; SizeZ_mm: 0.7mm; LuminousFlux_PhiV: 0.016-0.0295lm; Luminous Intensity: 4.5-9.7mcd; LambdaD: 570nm; Tjmax_C: 125°C; Angle: 120°; Led Orientation: Top View; Forward Current: 2mA; Vf_V: 1.8V; AEC Qualified: Yes; Vr_V: 12V
F1-F4 = CMP-0122960-1: 25 A 250 V AC 80 V DC Fuse Board Mount (Cartridge Style Excluded) Surface Mount 2-SMD, Square End Block; Manufacturer: Bourns; Interrupt_AC: 100A; Interrupt_DC: 130A; MeltingTyp: 625A2Sec; SizeZ_mm: 3.3mm; VAC_V: 250V; Fuse Speed: Fast; AEC Qualified: No; Fuse Current: 25A; Res_ohm: 0.0024Ω
L1 L2 L5 L6 = CMP-0127626-1: Boost Inductor TIDA-010957; Manufacturer: Bourns; AEC Qualified: No; DCR_ohm: 11.11m; Ind_H: 87µH; Isat: 42A; SizeZ_mm: 49.4mm; Value: 87uH; Test Frequency: 100kHz; Tolerance_%: 10%
L12 L19 = CMP-0127627-2: 4-Phase CMC; Manufacturer: Bourns; AEC Grade: NA; AEC Qualified: No; Imax_A: 25A; Ind_H: 3mH; SizeZ_mm: 30.3mm; Test Frequency: 100kHz; Tolerance_%: +50/-35%
Q1 = CMP-0000585-1: MOSFET, N-CH, 30 V, 22 A, DQK0006C (WSON-6); Alternate Manufacturer: None; Manufacturer: Texas Instruments; SizeZ_mm: 0.8; ChType: N; Value2: 2.4 nC; Value1: 0.02; VdsMax_V: 30V; SizeX_mm: 2; Vgs_V: 20V; Value: 30V; Rdson45_ohm: 0.029; SizeArea_mm2: 4; AEC Category: Q101; IdsMax_A: 22A; SizeAreaWB_mm2: 9; U/M: EA; QgTyp_nC: 2.4
R83 R85 R87 R92 = CMP-0097004-1: PTCEL Series 500 V 60 Ohm ±30 % Radial Inrush Current Limiter PTC Thermistor; Manufacturer: Vishay Bccomponents; Value: 60Ω; SizeZ_mm: 17mm; AEC Qualified: Yes; Hold Current: 120mA; Tolerance_%: 30%; VDC_V: 500V; AEC Grade: Grade 2
R89-R91 R94 = CMP-0096768-1: 5 kA Varistor 1 Circuit Through Hole Disc 17mm; Manufacturer: Bourns; AEC Qualified: No; SizeZ_mm: 23mm; VDC_V: 350V; Vc: 100A; ValueDisplayed: 40pF; Clamping Voltage: 730V
R96 = CMP-0026656-1: RES, 100, 1%, 0.1 W, 0402; Manufacturer: Panasonic; Power_W: 100mW; TempCo: 100 ppm/C; Value_Code: 100R; U/M: EA; Value: 100; EIA_Code: E96; SizeX_mm: 1; SizeY_mm: 0.5; SizeZ_mm: 0.6; Value2: 0.1W; VDC_V: 50V; AEC Category: Q200
R97 = CMP-0021998-4: as R284 on sheet TIDA-010957-DCAC-Switching-Stage-GaN
R220-R223 = CMP-0124381-1: Power Relay 12VDC 25A SPST-NO(30.1x15.7x23.3)mm THT; Manufacturer: FCL Components; Coil Power_W: 780mW; Coil Type: Non-Latching; Coil Voltage_VDC: 12V; SizeZ_mm: 23.6mm; AEC Qualified: No; Coil Resistance: 185Ω
R234 = CMP-0025936-5: RES, 680, 5%, 0.1 W, 0603; Manufacturer: Yageo; Power_W: 100mW; TempCo: 100 ppm/C; Value_Code: 680R; Value: 680; EIA_Code: E24; SizeX_mm: 1.6; SizeY_mm: 0.8; SizeZ_mm: 1; Value2: 0.1W; SizeArea_mm2: 1.28; AEC Qualified: N; VDC_V: 75V; AEC Category: Q200; SizeAreaWB_mm2: 4.68
TP2-TP4 TP7 = CMP-0055148-2: Test Point, Multipurpose, Black, TH; Manufacturer: Keystone Electronics; CNHeader: FALSE; ContactFinish: Silver; Green_REACh: Passed; Green_Lifecycle: Active; CT: TRUE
